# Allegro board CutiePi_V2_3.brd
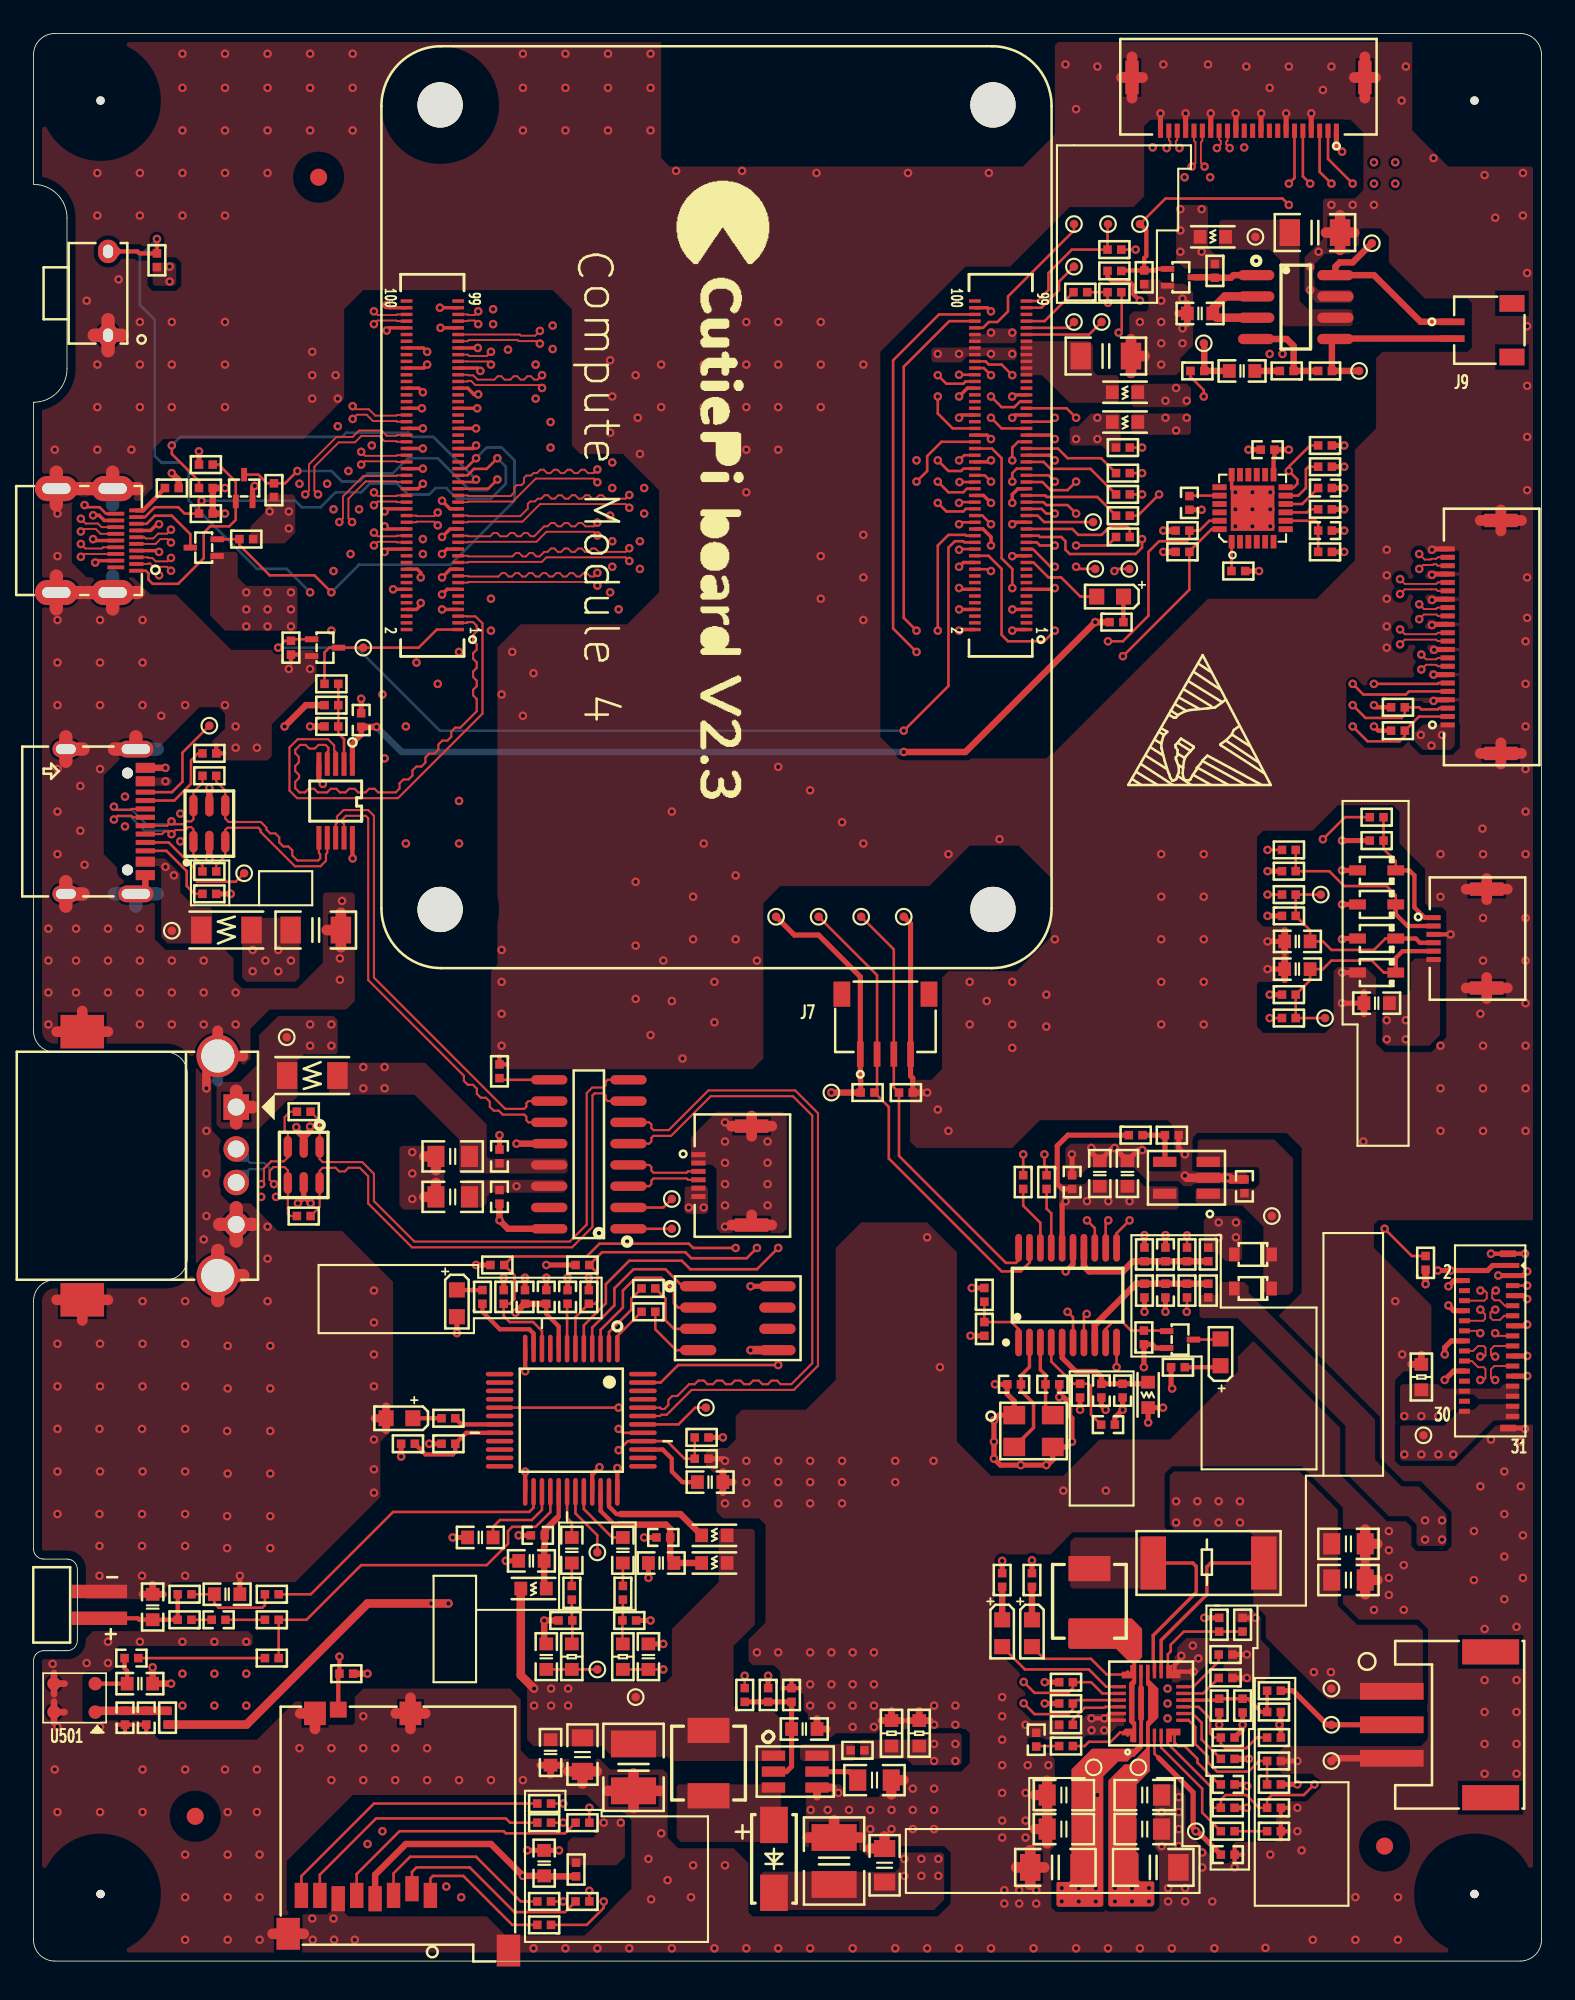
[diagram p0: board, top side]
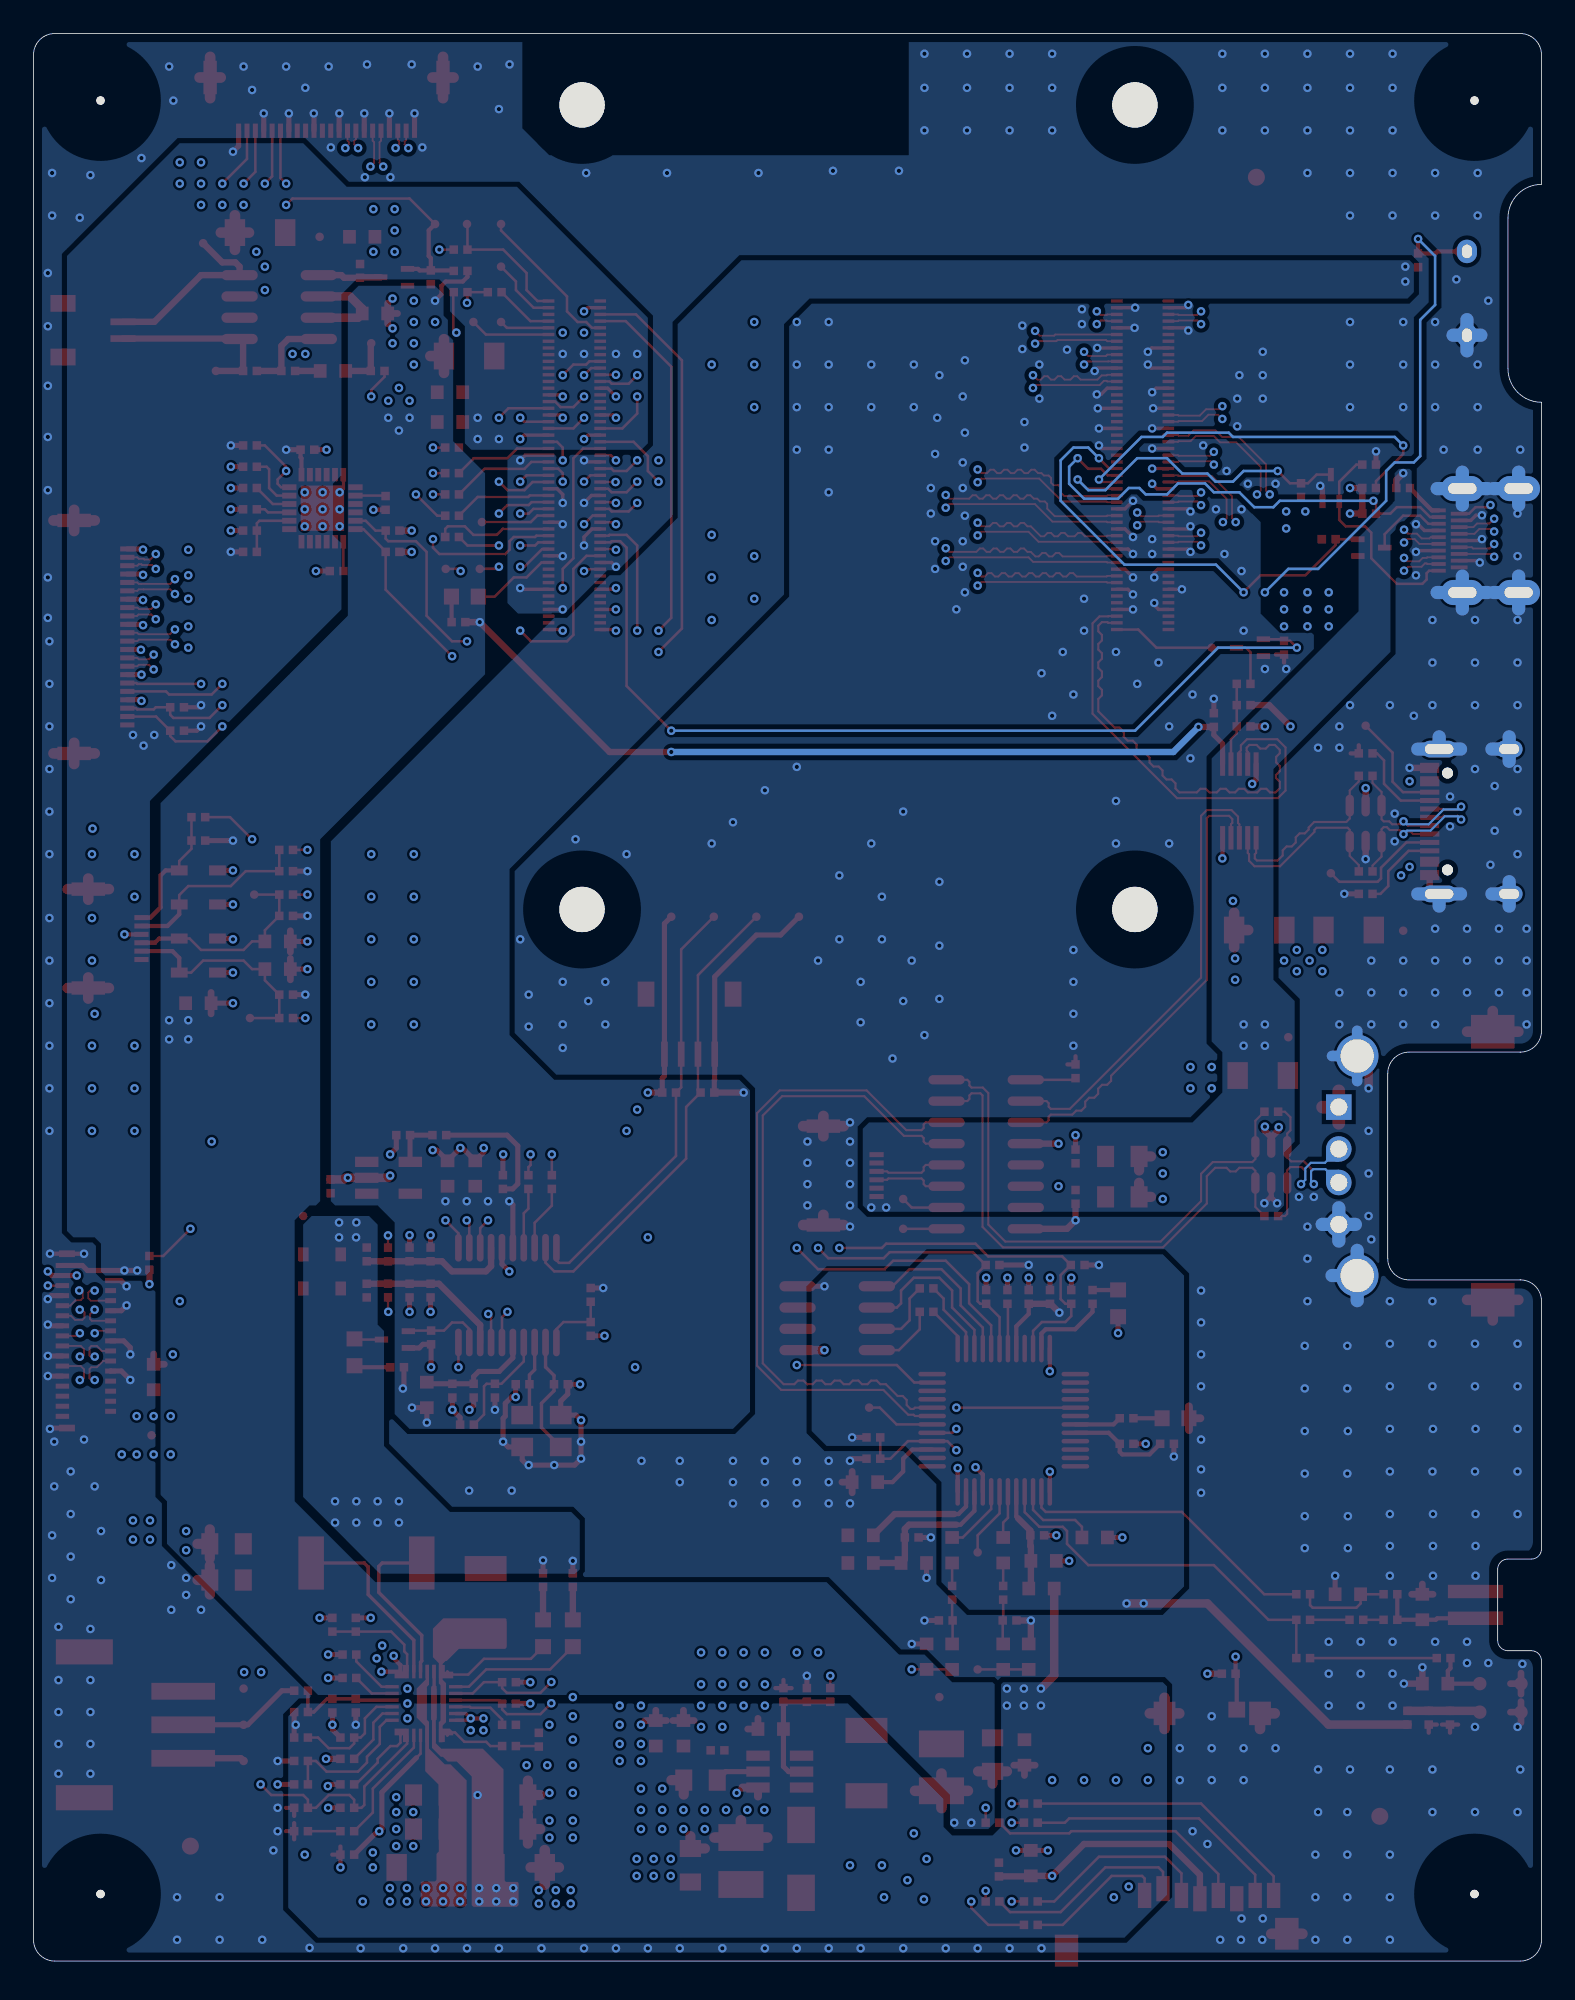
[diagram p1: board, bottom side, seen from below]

Outline 90.01 x 115 mm; copper layers: TOP, GND02, L03, L04, GND05, BOTTOM. Coordinates in mm from the lower left corner of the outline.
Outline path: 0,113.73 arc(0.37,114.63) 1.27,115 88.74,115 arc(89.64,114.63) 90.01,113.73 90.01,1.27 arc(89.64,0.37) 88.74,0 1.27,0 arc(0.37,0.37) 0,1.27 0,17.91 arc(0.18,18.34) 0.61,18.52 1.27,18.52 2.01,18.52 arc(2.44,18.7) 2.62,19.13 2.62,23.37 arc(2.44,23.8) 2.01,23.98 0.61,23.98 arc(0.18,24.16) 0,24.59 0,39.37 arc(0.37,40.27) 1.27,40.64 7.91,40.64 arc(8.81,41.01) 9.18,41.91 9.18,52.96 arc(8.81,53.86) 7.91,54.23 1.27,54.23 arc(0.37,54.6) 0,55.5 0,93 arc(1.41,93.59) 2,95 2,104 arc(1.41,105.41) 0,106 0,113.73

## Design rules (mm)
net group DP_N12951086: nets N12951060 N12951086
net group N13167521: nets N13167521 N13167621
net group RXD0: nets N12403491 RXD0
net group TXD0: nets N12403489 TXD0
net group USB1_: nets USB1_DM USB1_DP
net group USB2_: nets USB2_DM USB2_DP
net group USB3_DM: nets USB3_DM USB3_DP
net group USB_DP: nets USB_DN USB_DP
net group USBH_DP: nets USBH_DN USBH_DP
net group USBS_DN: nets USBS_DN USBS_DP
net group BOOST_EN: nets BOOST_EN CHARGE_EN N12951318
net group CAM0: nets CAM0_CN CAM0_CP CAM0_DN0 CAM0_DN1 CAM0_DP0 CAM0_DP1
net group CAM1: nets CAM1_CN CAM1_CP CAM1_DN0 CAM1_DN1 CAM1_DN2 CAM1_DN3 CAM1_DP0 CAM1_DP1 CAM1_DP2 CAM1_DP3
net group DSI1: nets DSI1_CN DSI1_CP DSI1_DN0 DSI1_DN1 DSI1_DN2 DSI1_DN3 DSI1_DP0 DSI1_DP1 DSI1_DP2 DSI1_DP3
net group HDMI1: nets HDMI_CK_N HDMI_CK_P HDMI_D0_N HDMI_D0_P HDMI_D1_N HDMI_D1_P HDMI_D2_N HDMI_D2_P
net group VBUSA: nets N12836963

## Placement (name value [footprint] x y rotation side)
C2  47u/6.3V  [C1206]  16.85 61.51 0 top
C17  -  [C0402]  19.56 74.04 270 top
C20  47u/6.3V  [C1206]  76.49 103.12 0 top
C24  4.7u/16V  [C0603]  30.48 5.84 90 top
C68  0.1uF/50V  [C0603]  30.86 12.45 270 top
C69  1.0uF/25V  [C0805]  32.77 12.32 270 top
C73  0.1uF/50V  [C0603]  46.01 13.84 0 top
C74  0.22uF/50V  [C0805]  50.2 10.79 0 top
C76  4.7uF/50V  [C1210]  47.79 5.97 90 top
C78  0.22uF/50V  [C0805]  50.8 5.71 90 top
C80  0.1uF/50V  [C0603]  80.17 57.15 180 top
C81  0.1uF/50V  [C0603]  75.44 60.83 180 top
C82  1000pF/50V  [C0603]  75.44 59.18 180 top
C85  4.7uF/50V  [C1210]  35.81 11.56 90 top
C86  4.7u/16V  [C0603]  69.63 98.3 180 top
C87  0.39u/16V  [C0603]  72.14 94.87 0 top
C383  -  [C0402]  77.09 85.34 0 top
C384  -  [C0402]  77.09 87.88 0 top
C385  -  [C0402]  73.66 90.17 180 top
C386  -  [C0402]  68.99 87 90 top
C2474  -  [C0402]  63.74 34.03 270 top
C2475  -  [C0402]  58.53 34.41 180 top
C2476  -  [C0402]  60.82 34.41 0 top
C2477  -  [C0402]  61.99 46.48 90 top
C2478  4.7u/16V  [C0603]  63.64 46.99 90 top
C2479  -  [C0402]  65.01 34.03 270 top
C2480  -  [C0402]  72.28 46.22 90 top
C2481  4.7u/16V  [C0603]  65.29 46.99 90 top
C2483  -  [C0402]  59.85 13.21 270 top
C2484  47u/6.3V  [C1206]  60.99 5.59 180 top
C2485  10u/16V  [C0805]  61.5 7.87 180 top
C2486  10u/16V  [C0805]  61.5 9.91 180 top
C2487  47u/6.3V  [C1206]  66.84 5.59 0 top
C2488  10u/16V  [C0805]  66.33 7.87 0 top
C2489  10u/16V  [C0805]  66.33 9.91 0 top
C2490  10u/16V  [C0805]  78.49 24.89 0 top
C2491  10u/16V  [C0805]  78.49 22.73 0 top
C2492  -  [C0402]  71.28 6.35 0 top
C2493  -  [C0402]  71.28 10.54 0 top
C2495  -  [C0402]  27.81 48.01 90 top
C2496  10u/16V  [C0805]  25.02 48.01 180 top
C2497  10u/16V  [C0805]  25.02 45.59 180 top
C2501  4.7u/16V  [C0603]  29.72 23.88 180 top
C2502  -  [C0402]  30.1 25.4 180 top
C2503  -  [C0402]  37.59 25.27 180 top
C2504  4.7u/16V  [C0603]  37.47 23.75 180 top
C2505  47u/6.3V  [C1206]  64.01 95.76 0 top
C2507  4.7u/16V  [C0603]  26.67 25.27 180 top
C2508  -  [C0402]  6.73 14.52 90 top
C2509  -  [C0402]  5.46 14.52 270 top
C2510  100pF  [C0603]  6.35 16.55 0 top
C2511  -  [C0402]  30.61 39.62 90 top
C2512  -  [C0402]  27.81 45.59 270 top
C2513  val*  [C0603]  40.39 28.57 0 top
C2514  -  [C0402]  29.34 39.62 90 top
C2515  -  [C0402]  31.88 39.62 90 top
C2516  val*  [C0603]  35.18 24.51 270 top
C2517  val*  [C0603]  36.7 18.16 270 top
C2518  val*  [C0603]  32.13 24.51 270 top
C2519  val*  [C0603]  30.61 18.16 90 top
C2520  val*  [C0603]  11.56 21.88 0 top
C2521  -  [C0402]  11.05 20.36 180 top
C2522  val*  [C0603]  7.11 21.12 90 top
C2523  -  [C0402]  64.14 32 0 top
C2524  -  [C0402]  5.84 18.07 180 top
C2525  -  [C0402]  67.56 42.16 90 top
C2526  -  [C0402]  67.56 40 270 top
D1  -  [LED0603]  64.26 81.41 0 top
D10  SS14-M3/61T  [DO-214AC]  44.2 6.1 90 top
D11  ESDLIN1524BJ  [SOD323]  80.17 63.04 0 top
D12  ESDLIN1524BJ  [SOD323]  80.17 65.07 0 top
D13  ESDLIN1524BJ  [SOD323]  80.17 58.97 0 top
D14  ESDLIN1524BJ  [SOD323]  80.17 61.01 0 top
D17  BAT54HT1  [DIO-SOD323]  72.79 40.13 180 top
D18  BAT54HT1  [DIO-SOD323]  72.79 42.16 180 top
D19  -  [LED0603]  70.85 36.32 270 top
D20  -  [LED0603]  57.82 19.56 90 top
D21  -  [LED0603]  59.6 19.56 90 top
D22  -  [LED0603]  25.27 39.24 90 top
D23  -  [LED0603]  21.84 32.38 0 top
F1  6V/2A  [1206]  11.51 61.51 0 top
F2  6V/0.5A  [1206]  16.64 52.83 180 top
FB2  BLM18PG121SH1  [SL0603]  70.39 102.87 0 top
FB7  BLM18PG121SH1  [SL0603]  66.53 33.78 90 top
FB8  BLM18PG121SH1  [SL0603]  40.64 23.75 0 top
FB9  BLM18PG121SH1  [SL0603]  29.84 22.23 180 top
FB10  BLM18PG121SH1  [SL0603]  65.15 93.6 180 top
FB12  BLM18PG121SH1  [SL0603]  65.15 91.82 180 top
FB13  val*  [SL0603]  40.64 25.4 0 top
J2  VAL  [TYPEC_6446_116FH1301]  4.02 67.99 270 top
J7  -  [SH1_0_4]  50.85 54.11 180 top
J9  -  [SH1_0_2]  84.67 97.3 90 top
J11  VAL  [CONFPC22_05MM_FH52_A]  86 79 90 top
J13  467651001  [MICRO_HDMI]  5.53 84.75 270 top
J14  -  [USB_AM]  12.1 47.45 0 top
J16  473521001_sd  [MOLEX_473521001]  21.78 7.81 0 top
J17  FH52-6S-0.5SH  [CONFPC6_05MM_FH52]  85.15 61 90 top
J21  FH26W-31S-0.3SHW  [CONFPC31_03MM_FH26W]  86.85 37 90 top
J23  VAL  [PH2_0_3]  81.07 14.1 270 top
J24  DF40C-100DS-0.4V  [FCI_10033853_CM]  57.73 89.24 270 top
J25  DF40C-100DS-0.4V  [FCI_10033853_CM]  23.81 89.24 270 top
J26  VAL  [CONFPC22_05MM_FH52_A]  72.52 110.79 180 top
J27  VAL  [MIC_4_5]  3.94 21.25 270 top
J28  VAL  [CONFPC6_05MM_FH52]  41.27 46.86 90 top
L5  10uH/20%  [SHC0402]  40.29 11.81 270 top
L634  1.5u  [SHC0402]  63.03 21.46 90 top
NOREF  val  [unnamed]  57.27 110.74 0 top
NOREF#2  -  [#2]  -58.9 96.01 0 top
NOREF#3  -  [#2]  41.4 90.09 270 top
NOREF#4  -  [unnamed]  17.02 106.43 0 top
NOREF#5  -  [#2]  -66.42 -5.33 0 top
NOREF#6  -  [unnamed]  4 4 0 top
NOREF#7  -  [#2]  40.77 86.74 0 top
NOREF#8  val  [unnamed]  24.27 62.74 0 top
NOREF#9  val  [unnamed]  24.27 110.74 0 top
NOREF#10  -  [unnamed]  4 111 0 top
NOREF#11  -  [#2]  -66.42 36.7 0 top
NOREF#12  -  [unnamed]  9.65 8.64 0 top
NOREF#13  val  [unnamed]  57.27 62.74 0 top
NOREF#14  -  [#2]  65.14 70.04 0 top
NOREF#15  -  [unnamed]  86.01 111 0 top
NOREF#16  -  [unnamed]  86.01 4 0 top
NOREF#17  -  [unnamed]  80.64 6.86 0 top
Q3  -  [SOT50P160X90-3N]  10.16 84.33 180 top
Q4  -  [SOT50P160X90-3N]  12.57 87.88 90 top
Q5  -  [SOT50P160X90-3N]  68.44 37.08 0 top
Q6  -  [SOT50P160X90-3N]  68.49 100.46 0 top
Q7  -  [SOT50P160X90-3N]  17.4 78.36 0 top
R3  -  [R0402]  64.64 79.88 0 top
R15  -  [R0402]  12.7 84.84 0 top
R16  -  [R0402]  81.44 74.8 0 top
R17  -  [R0402]  81.44 73.41 0 top
R18  -  [R0402]  14.35 87.76 270 top
R42  -  [R0402]  74.93 66.29 180 top
R43  -  [R0402]  80.17 68.25 180 top
R87  -  [R0402]  45.25 15.88 270 top
R88  -  [R0402]  42.45 15.88 90 top
R89  -  [R0402]  49.18 12.57 180 top
R90  3.3/1%  [R0603]  52.87 13.59 90 top
R91  3.3/1%  [R0603]  51.21 13.59 90 top
R114  -  [R0402]  74.93 65.02 180 top
R115  -  [R0402]  80.17 66.85 180 top
R117  -  [R0402]  74.93 62.36 0 top
R118  -  [R0402]  74.93 57.66 0 top
R120  -  [R0402]  74.93 56.26 180 top
R121  -  [R0402]  74.93 63.63 180 top
R122  -  [R0402]  16.13 44.45 180 top
R123  -  [R0402]  16.13 50.67 180 top
R124  -  [R0402]  70.52 100.84 270 top
R125  -  [R0402]  77.09 94.87 180 top
R126  -  [R0402]  74.8 94.87 180 top
R127  -  [R0402]  69.47 94.87 0 top
R272  -  [R0402]  62.47 34.03 270 top
R368  -  [R0402]  71.92 82.93 180 top
R370  -  [R0402]  77.09 84.07 180 top
R371  -  [R0402]  77.09 89.15 180 top
R373  -  [R0402]  77.09 86.61 180 top
R3039  -  [R0402]  56.75 37.71 270 top
R3040  -  [R0402]  56.75 39.75 90 top
R3041  -  [R0402]  60.47 46.48 270 top
R3042  -  [R0402]  59.07 46.48 270 top
R3043  -  [R0402]  49.78 51.82 0 top
R3044  -  [R0402]  52.07 51.82 0 top
R3049  -  [R0402]  67.94 49.28 180 top
R3051  -  [R0402]  65.79 49.28 0 top
R3052  -  [R0402]  70.12 42.16 90 top
R3053  -  [R0402]  66.31 42.16 90 top
R3054  -  [R0402]  7.37 101.47 270 top
R3057  -  [R0402]  83.09 41.66 90 top
R3058  -  [R0402]  8.26 87.88 0 top
R3059  -  [R0402]  66.28 37.21 90 top
R3060  -  [R0402]  68.31 35.43 0 top
R3061  -  [R0402]  66.29 100.46 90 top
R3062  -  [R0402]  10.29 89.28 0 top
R3063  NC_3.3/1%  [R0603]  82.84 34.84 90 top
R3064  -  [R0402]  70.12 40 270 top
R3065  -  [R0402]  66.31 40 270 top
R3066  -  [R0402]  43.85 15.88 270 top
R3086  -  [R0402]  74.04 13.34 180 top
R3087  -  [R0402]  61.63 12.83 0 top
R3088  -  [R0402]  71.28 13.34 180 top
R3089  20m/1W  [R2512]  70.14 23.75 0 top
R3090  -  [R0402]  74.04 11.94 180 top
R3091  -  [R0402]  74.04 10.54 0 top
R3092  -  [R0402]  74.04 9.14 180 top
R3093  -  [R0402]  71.28 9.14 0 top
R3094  -  [R0402]  61.63 16.64 180 top
R3095  -  [R0402]  57.82 22.73 90 top
R3096  -  [R0402]  61.63 15.37 180 top
R3097  -  [R0402]  71.28 12.06 0 top
R3098  -  [R0402]  74.04 16.13 180 top
R3099  -  [R0402]  61.63 14.1 0 top
R3100  -  [R0402]  59.6 22.73 90 top
R3101  -  [R0402]  70.77 15.24 90 top
R3102  -  [R0402]  70.77 20.07 270 top
R3103  -  [R0402]  72.17 15.24 90 top
R3104  -  [R0402]  72.17 20.07 270 top
R3105  -  [R0402]  71.28 7.75 180 top
R3106  -  [R0402]  71.15 16.89 180 top
R3107  -  [R0402]  71.15 18.29 180 top
R3108  -  [R0402]  74.04 7.75 0 top
R3132  -  [R0402]  18.67 17.14 0 top
R3133  -  [R0402]  10.5 72.05 0 top
R3134  -  [R0402]  10.5 63.67 0 top
R3137  -  [R0402]  74.04 14.86 180 top
R3138  -  [R0402]  30.48 2.16 180 top
R3139  -  [R0402]  32.77 3.56 180 top
R3140  -  [R0402]  30.48 3.56 180 top
R3141  -  [R0402]  32.77 8.26 180 top
R3142  -  [R0402]  30.48 8.26 180 top
R3143  -  [R0402]  30.48 9.4 180 top
R3145  -  [R0402]  64.52 100.84 180 top
R3149  -  [R0402]  27.81 53.09 270 top
R3153  -  [R0402]  32.38 5.46 270 top
R3154  -  [R0402]  68.85 42.16 90 top
R3155  -  [R0402]  68.85 40 270 top
R3156  -  [R0402]  62.48 99.57 180 top
R3157  -  [R0402]  65.02 90.3 0 top
R3158  -  [R0402]  8 14.52 90 top
R3160  -  [R0402]  33.15 39.62 270 top
R3161  -  [R0402]  10.5 70.71 0 top
R3162  -  [R0402]  10.5 65.01 0 top
R3163  -  [R0402]  17.78 73.66 0 top
R3164  -  [R0402]  17.78 74.93 180 top
R3165  -  [R0402]  68.58 85.34 180 top
R3166  -  [R0402]  68.58 84.07 180 top
R3167  -  [R0402]  77.09 90.42 180 top
R3168  -  [R0402]  10.29 87.88 0 top
R3169  -  [R0402]  10.29 86.36 0 top
R3172  -  [R0402]  17.78 76.2 0 top
R3173  -  [R0402]  32.77 41.53 180 top
R3174  -  [R0402]  36.7 38.73 180 top
R3175  -  [R0402]  36.7 40.13 180 top
R3176  -  [R0402]  27.69 41.53 180 top
R3177  -  [R0402]  28.07 39.62 270 top
R3178  -  [R0402]  26.8 39.62 90 top
R3179  -  [R0402]  24.77 32.38 180 top
R3180  -  [R0402]  22.35 30.86 180 top
R3181  -  [R0402]  24.77 30.86 0 top
R3182  -  [R0402]  39.88 31.24 0 top
R3183  -  [R0402]  39.88 29.97 180 top
R3184  val*  [R0603]  35.18 18.16 270 top
R3185  -  [R0402]  35.18 21.97 270 top
R3186  -  [R0402]  35.56 20.32 0 top
R3187  -  [R0402]  32.13 21.97 270 top
R3188  val*  [R0603]  32.13 18.16 270 top
R3189  -  [R0402]  31.75 20.32 0 top
R3190  -  [R0402]  14.22 21.88 180 top
R3191  -  [R0402]  9.02 20.36 180 top
R3192  -  [R0402]  9.02 21.88 180 top
R3193  -  [R0402]  64.52 102.11 180 top
R3194  -  [R0402]  65.02 88.77 180 top
R3195  -  [R0402]  65.02 87.5 180 top
R3196  -  [R0402]  15.37 78.36 90 top
R3197  -  [R0402]  65.02 84.96 0 top
R3198  -  [R0402]  65.02 86.23 180 top
R3199  -  [R0402]  14.22 18.07 180 top
R3200  -  [R0402]  14.22 20.36 180 top
R3201  -  [R0402]  64.52 99.57 0 top
SW2  TC-0143  [BUTTON]  4.45 99.5 270 top
TP28  VAL  [TESTPOINT_20MIL]  76.83 63.63 90 top
TP29  VAL  [TESTPOINT_20MIL]  77.09 56.26 90 top
TP30  VAL  [TESTPOINT_20MIL]  35.94 15.75 270 top
TP33  VAL  [TESTPOINT_20MIL]  82.96 31.37 0 top
TP41  VAL  [TESTPOINT_20MIL]  8.26 61.47 0 top
TP43  VAL  [TESTPOINT_20MIL]  63.28 11.56 0 top
TP44  VAL  [TESTPOINT_20MIL]  77.47 16.26 0 top
TP45  VAL  [TESTPOINT_20MIL]  69.38 7.75 0 top
TP46  VAL  [TESTPOINT_20MIL]  65.95 11.56 0 top
TP47  VAL  [TESTPOINT_20MIL]  77.47 14.1 0 top
TP52  VAL  [TESTPOINT_20MIL]  15.11 55.12 0 top
TP57  VAL  [TESTPOINT_20MIL]  72.93 102.87 90 top
TP58  VAL  [TESTPOINT_20MIL]  69.85 96.52 90 top
TP59  VAL  [TESTPOINT_20MIL]  66.04 103.63 90 top
TP60  VAL  [TESTPOINT_20MIL]  79.12 94.87 0 top
TP61  VAL  [TESTPOINT_20MIL]  79.88 102.49 0 top
TP62  VAL  [TESTPOINT_20MIL]  46.86 62.31 0 top
TP63  VAL  [TESTPOINT_20MIL]  49.4 62.31 0 top
TP64  VAL  [TESTPOINT_20MIL]  73.91 44.45 0 top
TP65  VAL  [TESTPOINT_20MIL]  47.62 51.82 0 top
TP77  VAL  [TESTPOINT_20MIL]  63.75 97.79 90 top
TP78  VAL  [TESTPOINT_20MIL]  62.1 97.79 90 top
TP79  VAL  [TESTPOINT_20MIL]  62.1 101.09 90 top
TP80  VAL  [TESTPOINT_20MIL]  64.14 103.63 90 top
TP81  VAL  [TESTPOINT_20MIL]  33.66 24.38 270 top
TP83  VAL  [TESTPOINT_20MIL]  62.1 103.63 90 top
TP84  VAL  [TESTPOINT_20MIL]  65.41 83.06 90 top
TP89  VAL  [TESTPOINT_20MIL]  63.37 83.06 90 top
TP90  VAL  [TESTPOINT_20MIL]  63.25 85.85 90 top
TP91  VAL  [TESTPOINT_20MIL]  77.47 11.94 0 top
TP92  VAL  [TESTPOINT_20MIL]  10.5 73.7 0 top
TP93  VAL  [TESTPOINT_20MIL]  12.57 64.9 0 top
TP94  VAL  [TESTPOINT_20MIL]  19.68 78.36 0 top
TP95  VAL  [TESTPOINT_20MIL]  40.13 33.02 180 top
TP97  VAL  [TESTPOINT_20MIL]  33.66 17.4 180 top
TP98  VAL  [TESTPOINT_20MIL]  44.32 62.31 0 top
TP99  VAL  [TESTPOINT_20MIL]  51.94 62.31 0 top
TP100  VAL  [TESTPOINT_20MIL]  38.1 43.69 90 top
TP101  VAL  [TESTPOINT_20MIL]  38.1 45.47 90 top
U3  CM108AH  [QFN48_05MM_0707MMLTS]  32.1 32.27 270 top
U5  IP4234CZ6  [TSOP6]  16.13 47.5 180 top
U6  -  [SOT23_6B]  45.47 11.3 270 top
U12  LM4871MX  [SOIC8_1D27MM]  75.34 98.68 270 top
U18  stm32f030f4p6  [TSSOP20_0D65MM]  61.72 39.73 0 top
U57  MPU6050  [QFN24_05MM_0404MML]  72.76 86.68 90 top
U60  -  [SOT23_5]  68.82 46.73 90 top
U501  -  [LGA5_CAV_4P1X3P1MM]  3.68 16.55 270 top
U580  AT93C46  [SOIC8]  42.04 38.35 270 top
U597  MP2636GR  [QFN-30]  66.71 15.37 90 top
U600  val  [SOP16_1P27_HS8836A]  33.15 48.13 90 top
U601  val  [TSOP6]  10.5 67.86 0 top
U602  -  [SOP10_20_120A]  18.03 69.22 180 top
Y2  -  [XTAL_3225_25M_A]  59.69 31.62 180 top

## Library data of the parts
C2 C20 C2484 C2487 C2505 = CAP_3216_6.3V_47u: Tolerance: tol*
C17 C383-C386 C2474 C2477 C2479 C2483 C2492 C2493 C2495 C2502 C2503 C2508 C2509 C2511 C2512 C2514 C2515 C2521 C2523-C2526 = CAP_1005_6.3V_100n
C24 C86 C87 C2478 C2481 C2501 C2504 C2507 C2513 C2516 C2518 C2520 = CAP_1608_6.3V_4.7u: Tolerance: tol*
C68 C69 C73 C74 C76 C78 C82 C85 C2510 C2517 C2519 C2522 = CAP: Tolerance: tol*
C80 C81 = CAP_0: Tolerance: tol*
C2475 C2476 = C_0603_22P/50V/5%
C2480 = CAP_1005_6.3V_1u
C2485 C2486 C2488-C2491 C2496 C2497 = CAP_2012_6.3V_10u: Tolerance: tol*
D1 = LED_1608_RED_0
D10 = S100: User Part Number: pn
D11-D14 = SMAJ30CA: User Part Number: PN
D17 D18 = DIODE_0: User Part Number: PN
D19-D23 = LED_1608_GREEN_0
F1 F2 = FUSE_POLY_2.0A_6V: Tolerance: tol*
FB2 FB7-FB10 FB12 FB13 = INDUCTOR_0: Tolerance: tol*; room: USB+5V
J2 = CON_HDMI_RA_3: User Part Number: PN
J7 = A2002WV-6P_7
J9 = A2002WV-6P_8
J11 J26 = CON_22W_FFC_0: User Part Number: PN
J13 = CON_HDMI_RA: User Part Number: PN
J14 = CON_USBA_RA_PTH_0
J16 = CON_uSD_2: User Part Number: PN
J17 J28 = A2002WV-6P_3: User Part Number: PN
J21 = CON32_1: User Part Number: PN
J23 = A2002WV-6P_4: User Part Number: PN
J24 J25 = CON_200W_DDR2SODIMM_CM_2: User Part Number: PN
J27 = A2002WV-6P_8: User Part Number: PN
L5 = IND: User Part Number: pn
L634 = IND_4u7_SRN4018-4R7M: User Part Number: pn
NOREF NOREF#8 NOREF#9 NOREF#13 = -: User Part Number: pn
Q3-Q7 = MOSFET_N_DMG1012T
R3 R3060 R3178 R3179 = RES_1005_470R
R15 R18 R3059 R3061 R3062 R3133 R3134 R3145 R3160 R3173 R3176 R3177 R3180-R3183 R3196 = RES_1005_100K
R16 R17 = RES_1005_1.8K
R42 R43 R87-R89 R120-R123 R127 R368 R370 R371 R373 R3052 R3057 R3064 R3066 R3086-R3088 R3090-R3093 R3095 R3097-R3108 R3137 R3149 R3153-R3158 R3161-R3164 R3167 R3172 R3174 R3175 R3185-R3187 R3189-R3195 R3197-R3201 = RES
R90 R91 R3063 R3089 R3184 R3188 = RES: Tolerance: tol*
R114 R115 R117 R118 R124-R126 R3049 R3051 R3053 R3065 R3165 R3166 R3168 R3169 = RES_0
R272 R3054 = R_0603_10K/5%
R3039 R3040 = R_0402_22R/5%
R3041 R3042 R3058 R3094 R3096 = R_1: signal model: DEFAULT_RESISTOR_0.001OHM_1_2
R3043 R3044 = R_0603/4.7K/5%
R3132 R3138-R3143 = RES_1005_47K
SW2 = SKEG_DIP2_2: User Part Number: PN
TP28-TP30 TP33 TP41 TP43-TP47 TP52 TP57-TP65 TP77-TP81 TP83 TP84 TP89-TP95 TP97-TP101 = Test pad: Tolerance: *; User Part Number: PN; room: P10-PMIC
U3 = LSD4WF-00007010_2: User Part Number: pn
U5 U601 = TMP100-Q1_0: User Part Number: pn
U6 = TPS61165TDB
U12 = SMD_EEPROM_SO8_0: User Part Number: pn
U18 = XF6000SYE_1: User Part Number: pn
U57 = TUSB1210BRHBT_2: User Part Number: PN
U60 = LP3470/SOT23_1
U501 = ADMP421_LGA5_1
U580 = PCA9306IDCURQ1_0: User Part Number: pn
U597 = STM8AF6226TA_5: User Part Number: PN
U600 = NEO-M8L_2: User Part Number: pn
U602 = IC_MUX2-1_USB_0
Y2 = X_0

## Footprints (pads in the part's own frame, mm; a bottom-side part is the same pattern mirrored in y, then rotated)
1206
  rect 1.219x1.6 smd: 1(-1.5,0) 2(1.5,0)
BUTTON
  oval 1.4x1.2 hole 0.8x0.6: 1(2.5,0) 2(-2.5,0)
C0402
  rect 0.508x0.508 smd: 1(-0.41,0) 2(0.41,0)
C0603
  rect 0.762x0.813 smd: 1(-0.76,0) 2(0.76,0)
C0805
  rect 1.016x1.27 smd: 1(-1,0) 2(1,0)
C1206
  rect 1.219x1.6 smd: 1(-1.5,0) 2(1.5,0)
C1210
  rect 1.6x2.692 smd: 1(-1.4,0) 2(1.4,0)
CONFPC6_05MM_FH52
  rect 0.3x0.85 smd: 1(1.25,1.587) 2(0.75,1.587) 3(0.25,1.587) 4(-0.25,1.587) 5(-0.75,1.587) 6(-1.25,1.587)
  rect 0.8x2 smd: 7(-2.95,-1.587) 8(2.95,-1.587)
CONFPC22_05MM_FH52_A
  rect 0.3x0.85 smd: 1(5.25,1.587) 2(4.75,1.587) 3(4.25,1.587) 4(3.75,1.587) 5(3.25,1.587) 6(2.75,1.587) 7(2.25,1.587) 8(1.75,1.587) 9(1.25,1.587) 10(0.75,1.587) 11(0.25,1.587) 12(-0.25,1.587) 13(-0.75,1.587) 14(-1.25,1.587) 15(-1.75,1.587) 16(-2.25,1.587) 17(-2.75,1.587) 18(-3.25,1.587) 19(-3.75,1.587) 20(-4.25,1.587) 21(-4.75,1.587) 22(-5.25,1.587)
  rect 0.8x2 smd: G1(-6.95,-1.587) G2(6.95,-1.587)
CONFPC31_03MM_FH26W
  rect 0.3x0.8 smd: 1(4.5,-1.437) 3(3.9,-1.437) 5(3.3,-1.437) 7(2.7,-1.437) 9(2.1,-1.437) 11(1.5,-1.437) 13(0.9,-1.437) 15(0.3,-1.437) 17(-0.3,-1.437) 19(-0.9,-1.437) 21(-1.5,-1.437) 23(-2.1,-1.437) 25(-2.7,-1.437) 27(-3.3,-1.437) 29(-3.9,-1.437) 31(-4.5,-1.437)
  rect 0.3x0.65 smd: 2(4.2,1.437) 4(3.6,1.437) 6(3,1.437) 8(2.4,1.437) 10(1.8,1.437) 12(1.2,1.437) 14(0.6,1.437) 16(0,1.437) 18(-0.6,1.437) 20(-1.2,1.437) 22(-1.8,1.437) 24(-2.4,1.437) 26(-3,1.437) 28(-3.6,1.437) 30(-4.2,1.437)
  rect 0.4x0.95 smd: G1(-5.2,-1.165) G2(5.2,-1.165)
DIO-SOD323
  rect 0.63x0.83 smd: 1(-1.115,0) 2(1.115,0)
DO-214AC
  rect 2.17x1.65 smd: A(2.025,0) C(-2.025,0)
FCI_10033853_CM
  rect 0.2x0.7 smd: 1(9.8,1.54) 2(9.8,-1.54) 3(9.4,1.54) 4(9.4,-1.54) 5(9,1.54) 6(9,-1.54) 7(8.6,1.54) 8(8.6,-1.54) 9(8.2,1.54) 10(8.2,-1.54) 11(7.8,1.54) 12(7.8,-1.54) 13(7.4,1.54) 14(7.4,-1.54) 15(7,1.54) 16(7,-1.54) 17(6.6,1.54) 18(6.6,-1.54) 19(6.2,1.54) 20(6.2,-1.54) 21(5.8,1.54) 22(5.8,-1.54) 23(5.4,1.54) 24(5.4,-1.54) 25(5,1.54) 26(5,-1.54) 27(4.6,1.54) 28(4.6,-1.54) 29(4.2,1.54) 30(4.2,-1.54) 31(3.8,1.54) 32(3.8,-1.54) 33(3.4,1.54) 34(3.4,-1.54) 35(3,1.54) 36(3,-1.54) 37(2.6,1.54) 38(2.6,-1.54) 39(2.2,1.54) 40(2.2,-1.54) 41(1.8,1.54) 42(1.8,-1.54) 43(1.4,1.54) 44(1.4,-1.54) 45(1,1.54) 46(1,-1.54) 47(0.6,1.54) 48(0.6,-1.54) 49(0.2,1.54) 50(0.2,-1.54) 51(-0.2,1.54) 52(-0.2,-1.54) 53(-0.6,1.54) 54(-0.6,-1.54) 55(-1,1.54) 56(-1,-1.54) 57(-1.4,1.54) 58(-1.4,-1.54) 59(-1.8,1.54) 60(-1.8,-1.54) 61(-2.2,1.54) 62(-2.2,-1.54) 63(-2.6,1.54) 64(-2.6,-1.54) 65(-3,1.54) 66(-3,-1.54) 67(-3.4,1.54) 68(-3.4,-1.54) 69(-3.8,1.54) 70(-3.8,-1.54) 71(-4.2,1.54) 72(-4.2,-1.54) 73(-4.6,1.54) 74(-4.6,-1.54) 75(-5,1.54) 76(-5,-1.54) 77(-5.4,1.54) 78(-5.4,-1.54) 79(-5.8,1.54) 80(-5.8,-1.54) 81(-6.2,1.54) 82(-6.2,-1.54) 83(-6.6,1.54) 84(-6.6,-1.54) 85(-7,1.54) 86(-7,-1.54) 87(-7.4,1.54) 88(-7.4,-1.54) 89(-7.8,1.54) 90(-7.8,-1.54) 91(-8.2,1.54) 92(-8.2,-1.54) 93(-8.6,1.54) 94(-8.6,-1.54) 95(-9,1.54) 96(-9,-1.54) 97(-9.4,1.54) 98(-9.4,-1.54) 99(-9.8,1.54) 100(-9.8,-1.54)
LED0603
  rect 0.9x0.95 smd: 1(0.8,0) 2(-0.8,0)
LGA5_CAV_4P1X3P1MM
  round 0.8 smd: 1(1.7,0) 2(1.7,-2.46) 3(0,-2.46) 4(0,0)
MIC_4_5
  rect 0.8x3.3 smd: 1(-0.8,0) 2(0.8,0)
MICRO_HDMI
  rect 0.23x0.85 smd: 1(1.8,0.612) 3(1.4,0.612) 5(1,0.612) 7(0.6,0.612) 9(0.2,0.612) 11(-0.2,0.612) 13(-0.6,0.612) 15(-1,0.612) 17(-1.4,0.612) 19(-1.8,0.612)
  rect 0.23x1 smd: 2(1.6,-0.612) 4(1.2,-0.612) 6(0.8,-0.612) 8(0.4,-0.612) 10(0,-0.612) 12(-0.4,-0.612) 14(-0.8,-0.612) 16(-1.2,-0.612) 18(-1.6,-0.612)
  oval 1.5x2.55 hole 0.65x1.7: 20(3.1,-4.163) 21(-3.1,-0.802) 22(3.1,-0.802) 23(-3.1,-4.163)
MOLEX_473521001
  rect 0.8x1.5 smd: 1(1.915,-3.898) 2(0.815,-3.498) 3(-0.285,-3.898) 4(-1.385,-4.098) 5(-2.485,-3.898) 6(-3.585,-4.098) 7(-4.685,-3.898) 8(-5.785,-3.898)
  rect 1x0.95 smd: 9(-3.585,7.187)
  rect 1.4x1.9 smd: 10(6.575,-7.187) 11(-6.575,-6.187)
  rect 1.3x1.4 smd: 12(-4.975,6.962) 13(0.725,6.962)
PH2_0_3
  rect 1.501x3.401 smd: (-4.351,5.9) (4.351,5.9)
  rect 1.001x3.8 smd: 1(-1.999,0) 2(0,0) 3(1.999,0)
QFN24_05MM_0404MML
  rect 0.8x0.35 smd: 1(-2,1.25) 2(-2,0.75) 3(-2,0.25) 4(-2,-0.25) 5(-2,-0.75) 6(-2,-1.25) 13(2,-1.25) 14(2,-0.75) 15(2,-0.25) 16(2,0.25) 17(2,0.75) 18(2,1.25)
  rect 0.35x0.85 smd: 7(-1.25,-1.975) 8(-0.75,-1.975) 9(-0.25,-1.975) 10(0.25,-1.975) 11(0.75,-1.975) 12(1.25,-1.975) 19(1.25,1.975) 20(0.75,1.975) 21(0.25,1.975) 22(-0.25,1.975) 23(-0.75,1.975) 24(-1.25,1.975)
  rect 2.7x2.6 smd: 25(0,0)
QFN48_05MM_0707MMLTS
  oval 1.65x0.27 smd: 1(-4.275,2.75) 2(-4.275,2.25) 3(-4.275,1.75) 4(-4.275,1.25) 5(-4.275,0.75) 6(-4.275,0.25) 7(-4.275,-0.25) 8(-4.275,-0.75) 9(-4.275,-1.25) 10(-4.275,-1.75) 11(-4.275,-2.25) 12(-4.275,-2.75) 25(4.275,-2.75) 26(4.275,-2.25) 27(4.275,-1.75) 28(4.275,-1.25) 29(4.275,-0.75) 30(4.275,-0.25) 31(4.275,0.25) 32(4.275,0.75) 33(4.275,1.25) 34(4.275,1.75) 35(4.275,2.25) 36(4.275,2.75)
  oval 0.27x1.65 smd: 13(-2.75,-4.275) 14(-2.25,-4.275) 15(-1.75,-4.275) 16(-1.25,-4.275) 17(-0.75,-4.275) 18(-0.25,-4.275) 19(0.25,-4.275) 20(0.75,-4.275) 21(1.25,-4.275) 22(1.75,-4.275) 23(2.25,-4.275) 24(2.75,-4.275) 37(2.75,4.275) 38(2.25,4.275) 39(1.75,4.275) 40(1.25,4.275) 41(0.75,4.275) 42(0.25,4.275) 43(-0.25,4.275) 44(-0.75,4.275) 45(-1.25,4.275) 46(-1.75,4.275) 47(-2.25,4.275) 48(-2.75,4.275)
QFN-30
  custom 0.175x0.175 smd: 1(-1.9,1.4) 8(-1.9,-1.4) 15(1.9,-1.4) 22(1.9,1.4)
  rect 0.8x0.2 smd: 2(-1.9,1) 3(-1.9,0.6) 4(-1.9,0.2) 5(-1.9,-0.2) 6(-1.9,-0.6) 7(-1.9,-1) 16(1.9,-1) 17(1.9,-0.6) 18(1.9,-0.2) 19(1.9,0.2) 20(1.9,0.6) 21(1.9,1)
  rect 0.2x0.8 smd: 9(-1,-1.9) 10(-0.6,-1.9) 11(-0.2,-1.9) 12(0.2,-1.9) 13(0.6,-1.9) 14(1,-1.9) 23(1,1.9) 24(0.6,1.9) 25(0.2,1.9) 26(-0.2,1.9) 27(-0.6,1.9) 28(-1,1.9)
  rect 1.8x0.3 smd: 29(0,0.6) 30(0,0)
R0402
  rect 0.508x0.508 smd: 1(-0.41,0) 2(0.41,0)
R0603
  rect 0.762x0.813 smd: 1(-0.76,0) 2(0.76,0)
R2512
  rect 1.524x3.175 smd: 1(-3.3,0) 2(3.3,0)
SH1_0_2
  rect 1x1.5 smd: (-1.6,-3.58) (1.6,-3.58)
  rect 0.4x1.5 smd: 1(0.5,0) 2(-0.5,0)
SH1_0_4
  rect 1x1.5 smd: (-2.6,-3.58) (2.6,-3.58)
  rect 0.4x1.5 smd: 1(1.5,0) 2(0.5,0) 3(-0.5,0) 4(-1.5,0)
SHC0402
  rect 1.5x2.5 smd: 1(-1.95,0) 2(1.95,0)
SL0603
  rect 0.762x0.813 smd: 1(-0.76,0) 2(0.76,0)
SOD323
  rect 1x0.6 smd: A(-1.14,0) C(1.14,0)
SOIC8
  oval 0.61x2.17 smd: 1(-1.905,-2.365) 2(-0.635,-2.365) 3(0.635,-2.365) 4(1.905,-2.365) 5(1.905,2.365) 6(0.635,2.365) 7(-0.635,2.365) 8(-1.905,2.365)
SOIC8_1D27MM
  oval 0.61x2.17 smd: 1(-1.905,-2.365) 2(-0.635,-2.365) 3(0.635,-2.365) 4(1.905,-2.365) 5(1.905,2.365) 6(0.635,2.365) 7(-0.635,2.365) 8(-1.905,2.365)
SOP10_20_120A
  rect 0.3x1.4 smd: 1(-1,-2.2) 2(-0.5,-2.2) 3(0,-2.2) 4(0.5,-2.2) 5(1,-2.2) 6(1,2.2) 7(0.5,2.2) 8(0,2.2) 9(-0.5,2.2) 10(-1,2.2)
SOP16_1P27_HS8836A
  oval 0.56x2.17 smd: 1(-4.445,-2.365) 2(-3.175,-2.365) 3(-1.905,-2.365) 4(-0.635,-2.365) 5(0.635,-2.365) 6(1.905,-2.365) 7(3.175,-2.365) 8(4.445,-2.365) 9(4.445,2.365) 10(3.175,2.365) 11(1.905,2.365) 12(0.635,2.365) 13(-0.635,2.365) 14(-1.905,2.365) 15(-3.175,2.365) 16(-4.445,2.365)
SOT23_5
  rect 0.61x1.397 smd: 1(-0.95,-1.3) 2(0,-1.3) 3(0.95,-1.3) 4(0.95,1.3) 5(-0.95,1.3)
SOT23_6B
  rect 0.61x1.397 smd: 1(-0.95,-1.3) 2(0,-1.3) 3(0.95,-1.3) 4(0.95,1.3) 5(0,1.3) 6(-0.95,1.3)
SOT50P160X90-3N
  rect 0.8x0.35 smd: 1(-0.8,0.5) 2(-0.8,-0.5) 3(0.8,0)
TESTPOINT_20MIL
  round 0.508 smd: 1(0,0)
TSOP6
  oval 0.5x1.3 smd: 1(-0.95,-1.075) 2(0,-1.075) 3(0.95,-1.075) 4(0.95,1.075) 5(0,1.075) 6(-0.95,1.075)
TSSOP20_0D65MM
  oval 0.4x1.65 smd: 1(-2.925,-2.825) 2(-2.275,-2.825) 3(-1.625,-2.825) 4(-0.975,-2.825) 5(-0.325,-2.825) 6(0.325,-2.825) 7(0.975,-2.825) 8(1.625,-2.825) 9(2.275,-2.825) 10(2.925,-2.825) 11(2.925,2.825) 12(2.275,2.825) 13(1.625,2.825) 14(0.975,2.825) 15(0.325,2.825) 16(-0.325,2.825) 17(-0.975,2.825) 18(-1.625,2.825) 19(-2.275,2.825) 20(-2.925,2.825)
TYPEC_6446_116FH1301
  round 0.65 hole 0.65 unplated: (-2.89,1.59) (2.89,1.59)
  rect 0.6x1.15 smd: A1_B12(-3.2,2.655) A4_B9(-2.4,2.655) B1_A12(3.2,2.655) B4_A9(2.4,2.655)
  rect 0.3x1.15 smd: A5(-1.25,2.655) A6(-0.25,2.655) A7(0.25,2.655) A8(1.25,2.655) B5(1.75,2.655) B6(0.75,2.655) B7(-0.75,2.655) B8(-1.75,2.655)
  oval 1x2.1 hole 0.6x1.7: G1(-4.32,2.09) G2(4.32,2.09)
  oval 1x1.6 hole 0.6x1.2: G3(-4.32,-2.09) G4(4.32,-2.09)
unnamed
  round 2.7 hole 2.7 unplated: (0,0)
USB_AM
  rect 1.524x1.524 hole 1.016: 1(0,3.5)
  round 1.524 hole 1.016: 2(0,1) 3(0,-1) 4(0,-3.5)
  round 2.54 hole 1.981: 5(-1.1,6.55) 6(-1.1,-6.55)
  rect 2.6x2 smd: 7(-9.189,8) 8(-9.189,-8)
XTAL_3225_25M_A
  rect 1.3x1.1 smd: 1(-1.15,-0.95) 2(1.15,-0.95) 3(1.15,0.95) 4(-1.15,0.95)

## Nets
3V3: C17.2 C80.1 FB12.1 J17.6 R3.1 R114.2 R115.2 R117.1 R118.1 R3066.1(A) R3145.2 R3153.1(A) U602.1(VCC)
3V3_SD: C24.1 J16.4(VDD) R3132.2 R3153.2(B)
5V_IN: C2.1 C2487.1 C2488.1 C2489.1 D17.2 F1.2(P2) R3064.2(B) R3091.2(B) R3093.2(B) R3164.2(B) TP46.1(PIN1) U597.4(VIN1) U597.19(VIN3) U597.30(VIN2) U601.5(PW)
GND: C2.2 C17.1 C20.2 C24.2 C68.2 C69.2 C73.2 C74.2 C76.2 C78.2 C80.2 C81.2 C82.2 C85.1 C86.2 C383.2 C384.2 C385.2 C386.1 C2474.2 C2475.2 C2476.2 C2477.2 C2478.2 C2479.2 C2480.2 C2481.2 C2483.1 C2484.2 C2485.2 C2486.2 C2487.2 C2488.2 C2489.2 C2490.2 C2491.2 C2492.2 C2493.2 C2495.2 C2496.2 C2497.2 C2501.2 C2502.2 C2503.2 C2504.2 C2505.2 C2507.2 C2508.1 C2509.2 C2510.2 C2511.2 C2512.2 C2513.2 C2514.2 C2515.2 C2517.1 C2519.2 C2520.2 C2522.2 C2523.2 C2525.2 C2526.2 D11.A D12.A D13.A D14.A D22.2(CATHODE) D23.2(CATHODE) J2.A1_B12(P1) J2.B1_A12(P16) J2.G1(SH1) J2.G2(SH2) J2.G3(SH3) J2.G4(SH4) J7.4 J11.1(P1) J11.4(P4) J11.7(P7) J11.10(P10) J11.13(P13) J11.16(P16) J11.19(P19) J11.G1 J11.G2 J13.4(P4) J13.7(P7) J13.10(P10) J13.13(P13) J13.16(P16) J13.20(SH1) J13.21(SH2) J13.22(SH3) J13.23(SH4) J14.4(P4) J14.5(P5) J14.6(P6) J14.7(P7) J14.8(P8) J16.6(VSS) J16.10(SH1) J16.11(SH2) J16.12(SH3) J16.13(SH4) J17.3 J17.7(G1) J17.8(G2) J21.4 J21.7 J21.10 J21.13 J21.16 J21.19 J21.22 J21.23 J21.G1 J21.G2 J23.3 J24.1 J24.2 J24.7 J24.8 J24.13 J24.14 J24.22 J24.23 J24.32 J24.33 J24.42 J24.43 J24.52 J24.53 J24.59 J24.60 J24.65 J24.66 J24.71 J24.74 J24.98 J25.7 J25.8 J25.13 J25.14 J25.19 J25.20 J25.25 J25.26 J25.31 J25.32 J25.37 J25.38 J25.44 J25.50 J25.55 J25.56 J25.61 J25.62 J25.67 J25.68 J25.73 J25.74 J25.79 J25.80 J25.85 J25.86 J25.91 J25.92 J25.97 J25.98 J26.1(P1) J26.4(P4) J26.7(P7) J26.10(P10) J26.13(P13) J26.16(P16) J26.19(P19) J26.G1 J26.G2 J27.1 J28.1 J28.2 J28.7(G1) J28.8(G2) Q4.2(S) Q5.2(S) Q6.2(S) Q7.2(S) R87.1(A) R90.2(B) R91.2(B) R368.1(A) R371.1(A) R373.1(A) R3039.2 R3044.2 R3049.1 R3053.2 R3059.1 R3061.1 R3062.1 R3063.2(B) R3065.2 R3088.1(A) R3090.1(A) R3092.1(A) R3099.1(A) R3103.1(A) R3104.1(A) R3106.1(A) R3107.1(A) R3108.2(B) R3133.2 R3134.2 R3149.1(A) R3160.1 R3163.1(A) R3177.1 R3181.1 R3183.1 R3186.2(B) R3189.1(A) R3196.1 SW2.1 TP91.1(PIN1) TP99.1(PIN1) U3.12(DVSS1) U3.25(AVSS1) U3.33(AVSS2) U3.36(DVSS2) U5.2(GND) U6.4(GND) U12.7(GND) U18.15(VSS) U57.18(GND) U57.25(G) U60.2(GND) U501.2(GND1) U501.3(GND2) U580.5(GND) U597.15(AGND) U597.27(PGND1) U597.28(PGND2) U600.16(GND) U601.2(GND) U602.5(GND) U602.10(O\E\) Y2.2 Y2.4
VBAT: C2490.1 C2491.1 D18.2 J23.1 R3052.2(B) R3089.2(B) R3095.2(B) R3097.2(B) R3100.2(B) TP44.1(PIN1) U597.17(BAT)
VBAT_AD: C2525.1 R3052.1(A) R3053.1 R3154.1(A) U18.14(ADC_9)
VBAT_AD_C: J24.94 R3154.2(B)
VBUS: C68.1 C69.1 C85.2 C2484.1 C2485.1 C2486.1 C2495.1 C2496.1 F2.1(P1) FB2.1 FB8.2 FB9.2 FB10.1 FB13.2 L5.1 Q3.1(G) R124.1 R3086.1(A) R3101.1(A) R3137.1(A) R3168.2 R3169.2 TP30.1(PIN1) TP43.1(PIN1) U6.1(VIN) U597.3(SYS1) U597.20(SYS3) U597.29(SYS2) U600.13(VCC)
VBUSA: F2.2(P2) J14.1(P1) J28.5 J28.6 R3058.2 TP52.1(PIN1) U5.5(PW)
VDD_AMP: C20.1 FB2.2 TP57.1(PIN1) U12.6(VDD)
VDDA: C2474.1 C2479.1 FB7.2 U18.5(VDDA)
AMP_SHUTDOWN: J24.45 Q6.1(G) R3061.2 R3145.1 TP59.1(PIN1)
AU_IN: C2517.2 R127.1(A) R3184.2(B)
BL_EN: R88.2(B) R3197.1(A)
BOOST_EN: R3094.1 U18.11(SPI1_CLK) U597.24(MODE)
BT_NDIS: J24.91 TP78.1(PIN1)
CAM0_CN: J25.40 J26.8(P8)
CAM0_CP: J25.42 J26.9(P9)
CAM0_DN0: J25.28 J26.2(P2)
CAM0_DN1: J25.34 J26.5(P5)
CAM0_DP0: J25.30 J26.3(P3)
CAM0_DP1: J25.36 J26.6(P6)
CAM0_IO0: J24.27 J26.17(P17)
CAM0_IO1: J24.26 J26.18(P18)
CAM1_CN: J11.8(P8) J25.27
CAM1_CP: J11.9(P9) J25.29
CAM1_DN0: J11.2(P2) J25.15
CAM1_DN1: J11.5(P5) J25.21
CAM1_DN2: J11.11(P11) J25.33
CAM1_DN3: J11.14(P14) J25.39
CAM1_DP0: J11.3(P3) J25.17
CAM1_DP1: J11.6(P6) J25.23
CAM1_DP2: J11.12(P12) J25.35
CAM1_DP3: J11.15(P15) J25.41
CAM1_IO0: J11.17(P17) J24.34
CAM1_IO1: J11.18(P18) J24.54
CAM_GPIO: J24.97 TP79.1(PIN1)
CHARGE_EN: R3096.1 U18.12(SPI1_MISO) U597.25(EN)
CM_1V8: J21.3 J24.88 J24.90 R3057.1(A)
CM_3V3: C385.1 FB12.2 J11.22(P22) J21.1 J21.2 J24.84 J24.86 J26.22(P22) R15.2 R16.1 R17.1 R18.2 R370.1(A) R3157.1(A) R3165.2 R3166.2 R3167.1(A) U57.13(VDD)
CM_5V: C2505.1 FB10.2 J24.77 J24.79 J24.81 J24.83 J24.85 J24.87
DSI1_CN: J21.14 J25.87
DSI1_CP: J21.15 J25.89
DSI1_DN0: J21.11 J25.75
DSI1_DN1: J21.17 J25.81
DSI1_DN2: J21.20 J25.93
DSI1_DN3: J21.8 J25.94
DSI1_DP0: J21.12 J25.77
DSI1_DP1: J21.18 J25.83
DSI1_DP2: J21.21 J25.95
DSI1_DP3: J21.9 J25.96
E2P_CS: U3.4(CS) U580.1(CS)
E2P_DI: R3174.1(A) U580.4(DO)
E2P_DO: R3175.1(A) U580.3(DI)
E2P_SK: U3.3(SK) U580.2(SK)
EEPROM_WP: J24.20 TP84.1(PIN1)
GLOBAL_EN: J24.99 R3193.2(B) TP80.1(PIN1)
GPIO12: J24.31 R3197.2(B)
GPIO13: J24.28 Q7.1(G) R3196.2
GPIO14: J24.55 R3194.2(B)
GPIO15: J24.51 R3195.2(B)
GPIO16: J24.29 R3201.2(B)
GPIO25: J24.41 R3198.2(B)
GPIO_VEF(IN): J24.78 R3157.2(B)
GYRO_INT: J24.48 R3167.2(B) U57.12(INT)
HDMI1_SCL: J13.17(P17) J25.47 R3169.1
HDMI1_SDA: J13.18(P18) J25.45 R3168.1
HDMI_CEC: J25.49 Q3.2(S) R15.1
HDMI_CK_N: J13.14(P14) J25.66
HDMI_CK_P: J13.12(P12) J25.64
HDMI_D0_N: J13.11(P11) J25.60
HDMI_D0_P: J13.9(P9) J25.58
HDMI_D1_N: J13.8(P8) J25.54
HDMI_D1_P: J13.6(P6) J25.52
HDMI_D2_N: J13.5(P5) J25.48
HDMI_D2_P: J13.3(P3) J25.46
HDMI_HPD: J13.1(P1) Q4.1(G) R3062.2
HDMI_HPD_N: J25.43 Q4.3(D) R18.1
ID_SC: J24.35 TP90.1(PIN1)
ID_SD: J24.36 TP89.1(PIN1)
IN2SYS_EN: R3092.2(B) R3093.1(A) U18.13(SPI1_MOSI) U597.7(PWIN)
LCD_RST: J21.5 J24.30 R3057.2(B)
LED0: R3178.1 U3.11(LED0)
LEDR: R3179.1 U3.19(LEDR)
LOL: C2518.1 U3.30(LOL)
LOR: C2516.1 U3.32(LOR)
MCU_3V3: C2477.1 C2478.1 C2481.1 FB7.1 J7.1 R272.2 R3040.2 R3043.1 R3051.1 R3054.2 R3060.1 TP65.1(PIN1) TP98.1(PIN1) U18.16(VDD) U60.5(OUT)
MCU_IND: Q5.1(G) R3059.2 U18.9(ADC_3)
MCU_REV1: R3193.1(A) R3198.1(A) U18.6(PA0)
MCU_REV2: R3156.1(A) R3201.1(A) U18.7(PA1)
MCU_RST: C2523.1 R272.1 U18.4(NRST)
MICIN: R3199.1(A) R3200.1(A) U3.28(MICIN)
MODE: J24.40 R3176.1 R3177.2 U3.10(MODE)
MSEL: J24.50 R3182.1 R3183.2 U3.40(MSEL)
MUTEP: J24.49 U3.17(MUTEP)
MUTER: J24.37 U3.5(MUTER)
NRPIBOOT: J24.93 R3156.2(B)
OSC_IN: C2475.1 U18.2(OSC_IN) Y2.3
OSC_OUT: C2476.1 U18.3(OSC_OUT) Y2.1
PI_NLED_ACTIVITY: D1.2(CATHODE) J24.21
PWRSEL: J24.39 R3160.2 R3173.1 U3.6(PWRSEL)
REG1V8: C2515.1 U3.7(DREG18)
REG3V3: C2511.1 C2514.1 R3158.1(A) R3173.2 R3176.2 R3180.2 R3182.2 U3.8(DREG33) U580.8(VCC)
RUN_PG: J24.92 TP83.1(PIN1)
RXD0: R3041.1 R3195.1(A)
SCL0: J11.20(P20) J24.80 J26.20(P20) R16.2
SCL5: J24.38 R3165.1 U57.23(SCL)
SCL6: J24.47 R43.2(B)
SDA0: J11.21(P21) J24.82 J26.21(P21) R17.2
SDA5: J24.44 R3166.1 U57.24(SDA)
SDA6: J24.46 R42.2(B)
SDX_CLK: J24.57 R3141.1
SDX_CMD: J24.62 R3140.1
SDX_D0: J24.63 R3142.1
SDX_D1: J24.67 R3143.1
SDX_D2: J24.69 R3138.1
SDX_D3: J24.61 R3139.1
SDX_DET: J16.9(DET) J24.76 R3132.1
SEL: R3163.2(B) R3164.1(A) R3172.2(B) U602.2(SEL)
SWCLK: J7.3 R3044.1 TP63.1(PIN1) U18.20(SWCLK)
SWDIO: J7.2 R3043.2 TP62.1(PIN1) U18.19(SWDIO)
SWITCH: R3054.1 SW2.2 U18.10(SPI1_CS)
TEST: R3180.1 R3181.2 U3.20(TEST)
TOUCH_INT_B: J24.25 R120.2(B)
TP_RST: J24.24 R121.2(B)
TXD0: R3042.1 R3194.1(A)
USB1_DM: R122.1(A) U5.6(C21) U600.7(DM1)
USB1_DP: R123.1(A) U5.1(C11) U600.8(DP1)
USB2_DM: U3.44(USBDM) U600.5(DM2)
USB2_DP: U3.43(USBDP) U600.6(DP2)
USB3_DM: J28.4 U600.3(DM3)
USB3_DP: J28.3 U600.4(DP3)
USB5V_AD: C2526.1 R3064.1(A) R3065.1 R3155.1(A) U18.8(ADC_2)
USB5V_AD_C: J24.96 R3155.2(B)
USB_DN: J25.3 U602.4(D-)
USB_DP: J25.5 U602.3(D+)
USBH_DN: U600.10(DM) U602.8(HSD2-)
USBH_DP: U600.11(DP) U602.9(HSD2+)
USBOTG_ID: J25.1 Q7.3(D) R3172.1(A) TP94.1(PIN1)
USBS_DN: R3161.2(B) U601.4(C22) U602.6(HSD1-)
USBS_DP: R3162.2(B) U601.3(C12) U602.7(HSD1+)
VBIAS: R3190.1(A) U3.26(VBIAS)
VD33: C2497.1 C2512.1 U600.12(DCP) U600.14(V33)
VLED+: C76.1 C78.1 D10.C J21.29 J21.30 J21.31 TP33.1(PIN1)
VLED-: J21.25 J21.26 J21.27 R89.1(A) R90.1(A) R91.1(A) R3063.1(A)
VOLDN: J24.56 U3.47(VOLDN)
VOLUP: J24.58 U3.41(VOLUP)
WL_NDIS: J24.89 TP77.1(PIN1)
N1478133: D11.C J17.2 R42.1(A) R114.1
N1478157: D12.C J17.1 R43.1(A) R115.1
N1478281: C81.1 D14.C J17.4 R117.2 R121.1(A) TP28.1(PIN1)
N1478289: C82.1 D13.C J17.5 R118.2 R120.1(A) TP29.1(PIN1)
N12332208: J9.2 R125.1 TP60.1(PIN1) U12.5(VO1)
N12332215: J9.1 TP61.1(PIN1) U12.8(VO2)
N12333733: Q6.3(D) R124.2 U12.1(SD)
N12334307: C86.1 U12.2(BP) U12.3(IN+)
N12334479: R125.2 R126.1 U12.4(IN-)
N12334672: C87.2 R126.2
N12335205: C87.1 R127.2(B) TP58.1(PIN1)
N12373140: R368.2(B) U57.1(CLKIN)
N12374321: C383.1 R370.2(B) U57.8(VLOGIC)
N12375648: C384.1 U57.10(REGOUT)
N12375668: R371.2(B) U57.11(FSYNC)
N12378079: C386.2 U57.20(CPOUT)
N12396095: R3039.1 R3040.1 U18.1(BOOT0)
N12403489: R3042.2 U18.18(U1_RX)
N12403491: R3041.2 U18.17(U1_TX)
N12412618: C2480.1 D17.1 D18.1 TP64.1(PIN1) U60.1(IN) U60.3(EN)
N12412734: R3049.2 R3051.2 U60.4(FB)
N12455509: J13.15(P15) Q3.3(D)
N12499716: D19.2(CATHODE) Q5.3(D)
N12720539: D10.A L5.2 U6.3(SW)
N12720829: C73.1 R87.2(B) R88.1(A) R3066.2(B) U6.2(CTRL)
N12720857: R89.2(B) U6.6(FB)
N12720893: C74.1 U6.5(COMP)
N12836963: J13.19(P19) R3058.1
N12951060: J14.2(P2) R122.2(B) U5.4(C22)
N12951086: J14.3(P3) R123.2(B) U5.3(C12)
N12951166: R3086.2(B) R3088.2(B) U597.11(FB)
N12951176: C2483.2 R3087.1(A)
N12951178: R3087.2(B) U597.1(IB)
N12951234: L634.1 U597.2(SW1) U597.21(SW2)
N12951240: L634.2 R3089.1(A) U597.18(CSP)
N12951278: R3090.2(B) R3091.1(A) U597.9(REG)
N12951318: C2492.1 R3094.2 R3096.2 R3102.1(A) TP45.1(PIN1) U597.5(VCC)
N12951326: D20.2(CATHODE) U597.23(C\H\G\)
N12951328: D20.1(ANODE) R3095.1(A)
N12951350: R3097.1(A) U597.10(A\C\O\K\)
N12951358: R3098.2(B) R3101.2(B) R3103.2(B) R3137.2(B) U597.12(NTC)
N12951362: J23.2 R3098.1(A) TP47.1(PIN1)
N12951368: R3099.2(B) U597.26(FREQ)
N12951370: D21.2(CATHODE) U597.22(B\O\O\S\T\)
N12951372: D21.1(ANODE) R3100.1(A)
N12951392: R3102.2(B) R3104.2(B) U597.16(VB)
N12951398: C2493.1 U597.8(TMR)
N12951408: R3105.2(B) U597.6(ILIM)
N12951410: R3106.2(B) U597.13(ISET)
N12951412: R3107.2(B) U597.14(OLIM)
N12951420: R3105.1(A) R3108.1(A)
N12951470: F1.1(P1) J2.A4_B9(P3) J2.B4_A9(P14) TP41.1(PIN1)
N12951488: J2.A5(P6) R3133.1
N12951490: J2.B5(P12) R3134.1
N12951536: J16.1(DAT2) R3138.2
N12951538: J16.2(CD/DAT3) R3139.2
N12951540: J16.3(CMD) R3140.2
N12951542: J16.5(CLK) R3141.2
N12951544: J16.7(DAT0) R3142.2
N12951546: J16.8(DAT1) R3143.2
N13080452: R3174.2(B) U3.1(DR)
N13080482: FB13.1 U3.35(DVDD)
N13080512: C2503.1 C2504.1 FB8.1 U3.34(AVDD2)
N13080672: C2501.1 C2502.1 FB9.1 U3.29(AVDD1)
N13097468: C2507.1 U3.27(VREF)
N13098112: C2508.2 C2509.1 R3158.2(B) U501.1(VDD)
N13104223: C2510.1 C2524.2 U501.4(OUTPUT)
N13115240: D1.1(ANODE) R3.2
N13167489: J2.B8(P5) TP92.1(PIN1)
N13167505: J2.A8(P11) TP93.1(PIN1)
N13167521: J2.A6(P8) J2.B6(P10) R3162.1(A) U601.1(C11)
N13167621: J2.A7(P9) J2.B7(P7) R3161.1(A) U601.6(C21)
N13191587: R3149.2(B) U600.9(REF)
N13218298: R3175.2(B) U3.2(DW)
N13235636: TP95.1(PIN1) U3.42(PDSW)
N13236221: C2513.1 U3.39(AREG36)
N13242775: C2516.2 R3185.1(A)
N13242801: R3184.1(A) R3185.2(B) R3186.1(A)
N13245751: C2519.1 R3188.2(B) TP97.1(PIN1)
N13245789: R3187.2(B) R3188.1(A) R3189.2(B)
N13245825: C2518.2 R3187.1(A)
N13254228: C2520.1 R3190.2(B) R3192.1(A)
N13255610: C2521.2 R3191.1(A)
N13255658: C2522.1 J27.2 R3191.2(B) R3192.2(B)
N13279315: C2524.1 R3199.2(B)
N13279395: C2521.1 R3200.2(B)
N13284349: TP100.1(PIN1) U600.1(DM4)
N13284361: TP101.1(PIN1) U600.2(DP4)
N123465088: R373.2(B) U57.9(AD0)
N124996560: D19.1(ANODE) R3060.2
N132243780: D22.1(ANODE) R3178.2
N132252170: D23.1(ANODE) R3179.2
N1308043429: TP81.1(PIN1) U3.31(LOBS)

Pads without a net: J13 2; J21 6 24 28; J24 3 4 5 6 9 10 11 12 15 16 17 18 19 64 68 70 72 73 75 95 100; J25 2 4 6 9 10 11 12 16 18 22 24 51 53 57 59 63 65 69 70 71 72 76 78 82 84 88 90 99 100; J26 11 12 14 15; U3 9 13 14 15 16 18 21 22 23 24 37 38 45 46 48; U57 2 3 4 5 6 7 14 15 16 17 19 21 22; U580 6 7; U600 15

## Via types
v1: diameter 0.508, hole 0.254, TOP to BOTTOM, 1146 vias

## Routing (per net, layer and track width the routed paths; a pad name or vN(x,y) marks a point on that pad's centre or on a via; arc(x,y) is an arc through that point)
3V3: length 59
  TOP w0.254: R3145.2 64.11,100.49 64.39,100.2 65.41,100.2 65.66,99.95 65.66,99.44 v1(66.04,99.06)
  TOP w0.305: R114.2 v1(73.66,65.02) ; U602.1 19.03,72.63 19.56,73.15 C17.2 ; R118.1 v1(73.79,57.66) ; v1(78.11,66.85) R115.2 ; R3066.1 v1(43.85,17.02) ; R117.1 v1(73.66,62.36)
  TOP w0.381: R3.1 v1(63.37,79.88) 55.63,72.14 v1(51.94,72.14) ; C17.2 v1(20.48,73.63)
  BOTTOM w0.381: v1(51.94,72.14) 21.97,72.14 v1(20.48,73.63)
  vias: v1(34.04,8.26) v1(35.05,8.26) v1(67.56,92.08) v1(68.2,91.31) v1(68.83,92.08) v1(80.77,56.13) v1(80.77,54.99) v1(81.92,56.13) v1(81.92,54.99)
3V3_SD: length 33.8
  TOP w0.381: R3132.2 v1(19.94,17.14) ; R3153.2 30.51,5.05 C24.1 v1(29.21,5.08) 27.31,6.99 22.23,6.99 20.39,5.15 J16.4
  L03 w0.381: v1(19.94,17.14) 20.7,16.38 20.7,10.03 22.1,8.64 25.66,8.64 v1(29.21,5.08)
5V_IN: length 18.1
  TOP w0.305: R3091.2 v1(75.44,10.54) ; v1(72.42,9.14) R3093.2
  TOP w0.381: R3164.2 16.26,74.93 v1(14.99,73.66) ; U601.5 v1(10.5,69.98)
  L03 w0.305: v1(75.44,10.54) 73.82,10.54 v1(72.42,9.14) 72.42,7.4 69.98,4.95 67.18,4.95 v1(66.58,4.36)
  vias: v1(13.08,60.33) v1(13.08,59.05) v1(13.84,59.69) v1(14.61,60.33) v1(14.61,59.05) v1(15.37,59.69) v1(64.55,4.36) v1(64.55,3.56) v1(65.57,4.36) v1(65.57,3.56) v1(66.58,3.56) v1(83.06,26.29) v1(83.06,25.15) v1(84.07,26.29) v1(84.07,25.15)
GND: length 598
  TOP w0.203: J24.42 56.7,87.44 v1(57.15,87) ; v1(24.38,87.12) 24.86,86.64 J25.37 ; v1(60.96,89.53) 60.65,89.84 J24.53 ; v1(23.5,95.25) 23.5,95.24 23.29,95.04 J25.80 ; v1(55.24,92.08) 55.41,92.24 J24.66 ; J25.62 v1(23.24,91.44) ; J24.43 58.76,87.84 58.42,87.5 v1(58.42,87) ; v1(20.95,85.6) 21.11,85.44 J25.32 ; v1(57.15,84.45) 57.15,84.96 56.67,85.44 J24.32 ; J25.79 26.5,95.04 v1(26.67,94.87) ; J25.55 26.23,90.24 v1(26.42,90.42) ; v1(57.15,90.81) 56.91,91.04 J24.60 ; v1(55.24,93.34) 55.74,93.84 J24.74 ; J24.52 57.06,89.44 v1(57.15,89.53) ; v1(58.42,83.82) 58.67,83.82 58.7,83.84 J24.23 ; v1(24.38,81.53) 24.69,81.84 J25.13 ; J25.8 22.86,80.64 23.11,80.9 v1(23.11,81.03) ; J13.7 7.42,84.15 v1(7.49,84.07) ; J25.20 22.91,83.04 23.11,82.84 v1(23.11,82.55) ; J25.14 v1(21.46,81.84) ; J25.74 23,93.84 v1(23.24,93.6) ; J25.56 v1(23.24,90.24) ; J13.10 3.64,84.75 v1(3.56,84.84) ; J13.13 6.99,85.35 7.37,85.72 v1(7.49,85.72) ; v1(20.95,84.07) 21.12,84.24 J25.26 ; J25.7 v1(24.38,80.64) ; J25.85 v1(26.52,96.24) ; v1(20.95,86.49) 21.11,86.64 J25.38 ; U597.28 64.03,14.37 v1(63.91,14.48) 64.2,14.77 U597.27 ; v1(58.42,92.08) 58.59,92.24 J24.65 ; J25.92 21.24,97.44 v1(21.08,97.28) ; v1(3.68,83.44) 3.79,83.55 J13.4 ; U57.18 71.51,87.85 v1(71.74,87.63) ; J13.16 4.22,85.95 3.91,86.26 v1(3.56,86.26) ; v1(58.42,85.72) 58.54,85.84 J24.33 ; v1(58.42,93.34) 58.52,93.44 J24.71 ; J25.44 22.94,87.84 v1(23.24,88.14) ; v1(24.38,83.95) 24.68,84.24 J25.25 ; v1(24.38,82.55) 24.88,83.04 J25.19 ; J24.22 55.5,83.44 v1(55.24,83.19) ; v1(23.5,96.01) 23.27,96.24 J25.86 ; J25.91 v1(24.29,97.44) ; v1(24.38,84.96) 24.86,85.44 J25.31 ; J24.7 v1(58.42,80.64) ; J24.1 58.49,79.44 v1(58.42,79.38) ; v1(26.54,93.47) 26.29,93.47 25.92,93.84 J25.73 ; J24.2 55.31,79.44 v1(55.24,79.38) ; J24.8 v1(55.25,80.64) ; J25.67 v1(26.49,92.64) ; v1(24.26,98.64) J25.97 ; J25.68 v1(23.18,92.64) ; J25.50 v1(23.24,89.04) ; v1(57.15,98.42) 56.93,98.64 J24.98 ; J25.61 v1(26.42,91.44) ; v1(55.24,81.92) 55.32,81.84 J24.14 ; v1(60.96,90.81) 60.72,91.04 J24.59 ; v1(21.08,98.81) 21.25,98.64 J25.98 ; v1(60.96,81.92) 60.89,81.84 J24.13
  TOP w0.254: U3.33 33.35,29.03 v1(33.78,29.46) ; C2492.2 71.69,6.83 ; C2492.2 71.69,5.87 ; C2492.2 72.17,6.35 ; v1(19.05,65.79) 19.03,65.8 U602.10 ; v1(68.51,18.21) 68.51,18.06 68.11,17.66 U597.15 v1(69.24,17.27) ; 74.45,7.26 R3108.2 ; R3108.2 74.45,8.23 ; R3108.2 74.93,7.75 ; 6.25,14.11 C2508.1 6.73,13.63 ; 28.3,53.5 R3149.1 27.81,53.98 ; v1(87,42.2) J21.G2 88.02,42.2 v1(89.03,42.2) ; C2509.2 5.94,14.11 ; C2509.2 4.98,14.11 ; C2509.2 5.46,13.63 ; 11.39,72.05 R3133.2 10.91,72.54 ; v1(84.58,61.25) J17.3 ; 15.37,77.47 R3196.1 15.85,77.95 ; 74.45,8.66 R3092.1 74.93,9.14 ; U3.36 v1(34.85,29.41) ; U3.25 v1(29.35,29.2) ; R87.1 45.73,16.29 ; R87.1 44.76,16.29 ; R87.1 45.25,16.77 ; v1(63.91,14.48) v1(63.15,14.48) ; U3.12 v1(29.35,35.19)
  TOP w0.305: C2511.2 v1(30.61,40.77) ; J11.4 83.52,82.75 v1(83.47,82.7) ; J11.10 83.52,79.75 v1(83.47,79.7) ; D12.A v1(78.11,65.07) ; R371.1 v1(78.23,89.15) ; v1(83.57,75.18) 83.63,75.25 J11.19 ; Q5.2 66.98,36.58 66.77,36.8 R3059.1 v1(66.28,35.43) ; v1(71.75,110.24) 71.77,110.22 J26.10 ; v1(68.77,110.24) 68.77,110.24 J26.4 ; J11.1 83.52,84.25 v1(83.47,84.2) ; C2476.2 v1(61.23,33.65) 61.47,33.65 61.85,33.27 61.85,32.51 61.98,32.38 v1(61.98,30.99) 61.98,30.98 61.68,30.67 Y2.4 60.84,29.9 60.53,29.59 v1(60.45,29.59) v1(58.93,29.59) 57.71,29.59 v1(57.33,29.97) v1(57.33,30.99) v1(57.33,32.27) 57.63,32.57 Y2.2 58.54,33.41 58.12,33.83 C2475.2 v1(57.39,34.41) ; v1(89.15,39.5) 88.95,39.7 J21.7 ; v1(72.44,10.44) 72.34,10.54 C2493.2 ; C80.2 v1(78.11,57.15) ; v1(83.47,81.2) 83.52,81.25 J11.7 ; R3183.1 41.15,29.97 v1(41.27,29.84) ; R3106.1 v1(72.42,16.89) ; J21.13 89.08,37.9 v1(89.15,37.97) ; C2502.2 v1(28.96,25.4) ; v1(63.14,48.51) 63.14,48.25 C2478.2 64.41,48.51 v1(64.53,48.51) 64.53,48.51 C2481.2 65.93,48.38 v1(66.18,48.38) ; v1(84.23,34.67) 84.77,35.2 85.41,35.2 J21.22 ; C2517.1 v1(37.59,18.92) ; J21.16 84.63,37 84.23,36.61 v1(84.23,36.2) ; v1(73.28,110.24) 73.27,110.22 J26.13 ; v1(29.46,6.6) C24.2 v1(31.37,6.6) ; R373.1 v1(78.23,86.61) ; J21.10 84.77,38.8 v1(84.45,39.12) ; v1(89.15,34.9) 89.15,34.9 J21.23 ; v1(25.02,25.27) C2507.2 ; C2495.2 v1(27.81,49.28) ; J11.13 83.62,78.25 v1(83.6,78.23) ; R3039.2 v1(55.93,37.3) ; R3181.1 v1(23.62,30.86) ; J26.19 v1(76.27,110.24) ; J21.G1 88.98,31.8 v1(89.03,31.75) ; C383.2 v1(78.23,85.34) ; C2523.2 64.55,32.43 v1(65.01,32.89) C2479.2 ; D11.A v1(78.11,63.04) ; TP99.1 52.35,61.9 J7.4 52.35,52.81 52.48,52.68 R3044.2 ; Q4.2 13.07,87.88 v1(13.21,88.01) ; C2477.2 61.99,48.12 v1(61.98,48.13) ; C82.2 v1(73.66,59.18) ; R368.1 v1(73.15,82.93) ; D14.A 78.15,61.01 v1(78.11,60.96) ; C2501.2 v1(28.19,23.88) ; R3186.2 v1(36.83,20.32) ; v1(17.27,70.23) 17.03,70.47 U602.5 ; R3088.1 72.17,13.81 v1(72.17,14.1) R3103.1 ; v1(89.15,36.1) 89.15,36.1 J21.19 ; R3062.1 v1(9.88,90.07) ; J21.4 84.8,40.6 v1(84.45,40.26) ; R3090.1 v1(75.44,11.94) ; R3177.1 v1(28.07,40.77) ; C2520.2 v1(12.32,22.99) ; D13.A v1(78.11,58.97) ; D22.2 v1(25.27,37.47) ; v1(61.61,41.14) 62.05,41.58 U18.15 ; C2514.2 v1(29.34,40.77) ; v1(67.56,38.73) C2526.2 ; C2474.2 63.74,33.14 v1(63.99,32.89) ; C81.2 v1(73.66,60.83) ; R3065.2 v1(66.31,38.73) ; R3134.2 v1(11.77,63.67) ; C2525.2 v1(67.56,43.31) ; J26.1 v1(67.27,110.24) ; R3104.1 v1(72.93,20.48) ; C2515.2 v1(31.88,40.77) ; C2504.2 v1(36.71,22.86) ; v1(66.31,43.31) R3053.2 ; v1(68.72,48.13) 68.36,48.5 R3049.1 ; C386.1 v1(69.72,86.58) ; J26.16 v1(74.77,110.24) ; C17.1 v1(19.56,75.31) ; J26.7 v1(70.27,110.24) ; C385.2 v1(72.52,90.17) ; C384.2 v1(78.23,87.88) ; R3160.1 v1(33.15,40.77) ; R3107.1 v1(72.42,18.29) ; J11.16 v1(83.57,76.75) ; C2503.2 v1(36.45,25.27)
  TOP w0.381: C2512.2 v1(27.81,44.2) 28.32,43.69 U600.16 ; J2.B1_A12 6.67,64.05 6.29,63.67 J2.G2 ; J2.A1_B12 v1(7.87,71.19) ; 16.13,49.15 15.68,49.59 v1(15.68,49.75) ; 16.13,49.15 U5.2 ; 16.13,49.15 16.51,49.53 v1(16.51,49.78) ; U601.2 v1(10.5,65.75) ; C2519.2 30.48,19.05 v1(30.48,20.32) R3189.1 ; v1(8.21,16.55) C2510.2 v1(7.11,17.52) ; TP91.1 77.63,12.1 J23.3 ; R3044.2 v1(53.34,51.82) ; R3163.1 v1(16.51,73.66)
  TOP w0.4: 1.22,15.92 U501.3 ; U501.3 1.85,16.55 ; U501.3 1.22,17.18 ; 1.22,14.22 U501.2 ; U501.2 1.85,14.85 ; U501.2 1.22,15.48
  TOP w0.405: 74.68,60.2 C81.2 74.68,61.47 ; 50.58,14.35 R91.2 ; R91.2 51.21,14.96 ; R91.2 51.85,14.35 ; C2522.2 7.11,22.49 ; C2522.2 7.75,21.88 ; C2522.2 6.48,21.88 ; C68.2 31.5,11.69 ; C68.2 30.86,11.08 ; C68.2 30.23,11.69 ; C2513.2 41.76,28.57 ; C2513.2 41.15,29.21 ; C2513.2 41.15,27.94 ; 52.23,14.35 R90.2 ; R90.2 52.87,14.96 ; R90.2 53.5,14.35 ; 74.68,58.55 C82.2 74.68,59.82 ; 47.38,13.84 C73.2 46.77,14.48 ; 68.87,97.69 C86.2 ; C86.2 68.28,98.3 ; C86.2 68.87,98.91 ; 79.41,57.79 C80.2 79.41,56.51 ; 82.84,36.21 R3063.2 82.2,35.6
  TOP w0.474: D23.2 21.04,33.09 ; D23.2 21.04,31.68 ; D23.2 20.37,32.38
  TOP w0.477: 47.69,10.35 U6.4 46.77,9.82
  TOP w0.508: J14.5 10.32,53.32 v1(10.32,52.07) ; U580.5 v1(42.8,36.45) ; v1(68.72,46.86) 68.85,46.73 U60.2 v1(71.25,46.73) 71.39,46.73 71.49,46.63 C2480.2
  TOP w0.61: 23.31,48.01 C2496.2 24.02,47.17 ; 79.49,24.03 C2490.2 ; C2490.2 79.49,25.76 ; C2490.2 80.22,24.89 ; 23.31,45.59 C2497.2 24.02,46.43 ; 79.49,21.87 C2491.2 ; C2491.2 80.22,22.73 ; C2491.2 79.49,23.6 ; 51.93,10.79 C74.2 51.2,9.93 ; 49.94,6.71 C78.2 50.8,7.45 ; 32.77,10.58 C69.2 ; C69.2 33.63,11.32 ; C69.2 31.9,11.32 ; 60.5,7.01 C2485.2 ; C2485.2 59.76,7.87 ; C2485.2 60.5,8.74 ; 59.76,9.91 C2486.2 ; C2486.2 60.5,9.04 ; C2486.2 60.5,10.77
  TOP w0.635: 85.51,58.05 J17.7 ; J17.7 86.74,58.68 ; J17.7 86.74,57.43 ; J17.7 87.97,58.05 ; 11,55.5 J14.5 12.5,54 ; C76.2 47.79,8.4 ; C76.2 49.36,7.37 ; C76.2 46.21,7.37 ; 35.81,9.13 C85.1 ; C85.1 35.81,11.19 ; C85.1 34.24,10.16 ; C85.1 37.39,10.16 ; 16.13,1.63 J16.11 14.27,1.63 ; 16.8,13.85 J16.12 15.92,14.78 ; J17.8 86.74,64.58 ; J17.8 87.97,63.95 ; J17.8 85.51,63.95 ; J17.8 86.74,63.33 ; 59.49,4.56 C2484.2 ; C2484.2 58.65,5.59 ; C2484.2 60.33,5.59 ; C2484.2 59.49,6.62 ; J14.8 4.44,39.45 ; J14.8 2.91,38.22 ; J14.8 1.38,39.45 ; J16.13 22.5,15.71 ; J16.13 23.38,14.78 ; J16.13 22.5,13.85 ; J16.13 21.62,14.78 ; 65.51,94.75 C2505.2 ; C2505.2 65.51,96.76 ; C2505.2 66.32,95.76 ; 18.35,60.48 C2.2 ; C2.2 17.51,61.51 ; C2.2 18.35,62.54 ; J14.7 2.91,56.68 ; J14.7 4.44,55.45 ; J14.7 1.38,55.45 ; 77.99,102.1 C20.2 ; C20.2 77.99,104.15 ; C20.2 78.83,103.12 ; C20.2 77.15,103.12
  TOP w0.64: J26.G2 66.2,112.38 ; J26.G2 64.94,112.38 ; J26.G2 65.57,111.15 ; J26.G2 65.57,113.6 ; 87.58,85.32 J11.G2 ; J11.G2 87.58,86.58 ; J11.G2 88.81,85.95 ; J11.G2 86.36,85.95 ; 79.47,111.15 J26.G1 ; J26.G1 79.47,113.6 ; J26.G1 80.1,112.38 ; J26.G1 78.84,112.38 ; J28.8 42.86,50.42 ; J28.8 42.86,49.21 ; J28.8 41.66,49.81 ; J28.8 44.07,49.81 ; J28.7 42.86,44.52 ; J28.7 44.07,43.91 ; J28.7 41.66,43.91 ; J11.G1 88.81,72.05 ; J11.G1 86.36,72.05 ; J11.G1 87.58,71.42 ; J11.G1 87.58,72.68
  TOP w0.787: J14.4 12.1,44.94 ; J14.4 11.11,43.95 ; J14.4 12.1,42.96 ; J14.4 13.09,43.95 ; J2.G4 1.93,64.4 ; J2.G4 2.96,63.67 ; J2.G4 1.93,62.94 ; 1.36,86.87 J13.23 ; J13.23 2.87,87.85 ; J13.23 1.36,88.83 ; J14.6 11,42.4 ; J14.6 11,39.4 ; J14.6 12.5,40.9 ; 3.22,81.65 J13.22 ; J13.22 4.72,80.67 ; J13.22 6.23,81.65 ; 4.83,72.31 J2.G1 6.11,73.04 ; J2.G3 2.96,72.31 ; J2.G3 1.93,73.04 ; J2.G3 1.93,71.58 ; J13.21 4.72,88.83 ; J13.21 6.23,87.85 ; J13.21 3.22,87.85 ; SW2.1 4.45,97.93 ; SW2.1 4.45,96.07 ; SW2.1 5.28,97 ; SW2.1 3.62,97 ; 1.36,80.67 J13.20 ; J13.20 2.87,81.65 ; J13.20 1.36,82.63
  GND02 w0.635: 11,52.53 J14.5 ; J14.5 11,55.47 ; J14.5 12.47,54
  GND02 w0.813: J13.23 1.36,88.8 ; J13.23 1.36,86.9 ; J13.23 2.84,87.85 ; 4.45,96.1 SW2.1 ; SW2.1 5.25,97 ; SW2.1 4.45,97.9 ; SW2.1 3.65,97 ; 11.13,43.95 J14.4 ; J14.4 12.1,42.98 ; J14.4 13.07,43.95 ; J14.4 12.1,44.92 ; 4.72,80.7 J13.22 ; J13.22 4.72,82.6 ; J13.22 6.2,81.65 ; J13.22 3.25,81.65 ; 4.72,86.9 J13.21 ; J13.21 6.2,87.85 ; J13.21 4.72,88.8 ; J13.21 3.25,87.85 ; 4.86,72.31 J2.G1 ; J2.G1 6.11,73.01 ; J2.G1 7.36,72.31 ; 4.86,63.67 J2.G2 ; J2.G2 7.36,63.67 ; J2.G2 6.11,62.97 ; 0.93,63.67 J2.G4 ; J2.G4 1.93,62.97 ; J2.G4 1.93,64.37 ; J2.G4 2.93,63.67 ; J14.6 11,42.37 ; J14.6 12.47,40.9 ; J14.6 11,39.43 ; 1.93,71.61 J2.G3 ; J2.G3 1.93,73.01 ; J2.G3 0.93,72.31 ; J2.G3 2.93,72.31 ; J13.20 2.84,81.65 ; J13.20 1.36,80.7 ; J13.20 1.36,82.6
  L03 w0.635: 11,52.53 J14.5 11,55.47
  L03 w0.78: 0.93,72.31 J2.G3 ; J2.G3 2.93,72.31 ; J2.G3 1.93,71.61 ; J2.G3 1.93,73.01 ; 4.86,63.67 J2.G2 ; J2.G2 7.36,63.67 ; J2.G2 6.11,62.97 ; 4.86,72.31 J2.G1 ; J2.G1 7.36,72.31 ; J2.G1 6.11,73.01 ; 0.93,63.67 J2.G4 ; J2.G4 1.93,64.37 ; J2.G4 2.93,63.67 ; J2.G4 1.93,62.97 ; J13.23 1.36,88.8 ; J13.23 2.84,87.85 ; J13.23 1.36,86.9 ; 4.72,80.7 J13.22 ; J13.22 3.25,81.65 ; J13.22 6.2,81.65 ; J13.22 4.72,82.6 ; SW2.1 5.25,97 ; SW2.1 4.45,97.9 ; SW2.1 3.65,97 ; SW2.1 4.45,96.1 ; 1.36,80.7 J13.20 ; J13.20 1.36,82.6 ; J13.20 2.84,81.65 ; J14.4 12.1,44.92 ; J14.4 13.07,43.95 ; J14.4 11.13,43.95 ; J14.4 12.1,42.98 ; 4.72,88.8 J13.21 3.25,87.85 ; J14.6 11,42.37 ; J14.6 11,39.43 ; J14.6 12.47,40.9
  L04 w0.635: 11,52.53 J14.5 ; J14.5 12.47,54 ; J14.5 11,55.47
  L04 w0.78: J13.23 1.36,88.8 ; J13.23 2.84,87.85 ; J13.23 1.36,86.9 ; 1.36,80.7 J13.20 ; J13.20 2.84,81.65 ; J13.20 1.36,82.6 ; J2.G1 7.36,72.31 ; J2.G1 6.11,73.01 ; J2.G1 4.86,72.31 ; J14.4 12.1,44.92 ; J14.4 13.07,43.95 ; J14.4 11.13,43.95 ; J14.4 12.1,42.98 ; 0.93,72.31 J2.G3 ; J2.G3 2.93,72.31 ; J2.G3 1.93,71.61 ; J2.G3 1.93,73.01 ; SW2.1 4.45,97.9 ; SW2.1 3.65,97 ; SW2.1 5.25,97 ; SW2.1 4.45,96.1 ; 3.25,81.65 J13.22 ; J13.22 6.2,81.65 ; J13.22 4.72,82.6 ; J13.22 4.72,80.7 ; 4.86,63.67 J2.G2 ; J2.G2 7.36,63.67 ; J2.G2 6.11,62.97 ; J13.21 6.2,87.85 ; J13.21 4.72,88.8 ; J13.21 3.25,87.85 ; 11,39.43 J14.6 ; J14.6 12.47,40.9 ; J14.6 11,42.37 ; J2.G4 2.93,63.67 ; J2.G4 0.93,63.67 ; J2.G4 1.93,62.97 ; J2.G4 1.93,64.37
  GND05 w0.635: 11,52.53 J14.5 ; J14.5 12.47,54 ; J14.5 11,55.47
  GND05 w0.813: 0.93,72.31 J2.G3 ; J2.G3 1.93,73.01 ; J2.G3 2.93,72.31 ; J2.G3 1.93,71.61 ; SW2.1 4.45,97.9 ; SW2.1 5.25,97 ; SW2.1 3.65,97 ; SW2.1 4.45,96.1 ; 6.11,62.97 J2.G2 ; J2.G2 4.86,63.67 ; J2.G2 7.36,63.67 ; 1.36,80.7 J13.20 ; J13.20 2.84,81.65 ; J13.20 1.36,82.6 ; 12.1,42.98 J14.4 ; J14.4 13.07,43.95 ; J14.4 12.1,44.92 ; J14.4 11.13,43.95 ; 4.72,80.7 J13.22 ; J13.22 3.25,81.65 ; J13.22 6.2,81.65 ; J13.22 4.72,82.6 ; J2.G4 2.93,63.67 ; J2.G4 0.93,63.67 ; J2.G4 1.93,62.97 ; J2.G4 1.93,64.37 ; 4.86,72.31 J2.G1 ; J2.G1 7.36,72.31 ; J2.G1 6.11,73.01 ; 1.36,86.9 J13.23 ; J13.23 2.84,87.85 ; J13.23 1.36,88.8 ; J13.21 6.2,87.85 ; J13.21 4.72,88.8 ; J13.21 3.25,87.85 ; J13.21 4.72,86.9 ; 11,39.43 J14.6 ; J14.6 11,42.37 ; J14.6 12.47,40.9
  BOTTOM w0.635: J14.5 12.5,54 ; J14.5 11,52.5 ; J14.5 11,55.5
  BOTTOM w0.787: 3.62,97 SW2.1 ; SW2.1 4.45,96.07 ; SW2.1 4.45,97.93 ; SW2.1 5.28,97 ; J14.6 11,42.4 ; J14.6 12.5,40.9 ; J14.6 11,39.4 ; 4.72,80.67 J13.22 ; J13.22 6.23,81.65 ; J13.22 4.72,82.63 ; J13.22 3.22,81.65 ; J2.G4 2.96,63.67 ; J2.G4 1.93,62.94 ; J2.G4 1.93,64.4 ; J13.23 2.87,87.85 ; J13.23 1.36,88.83 ; J13.23 1.36,86.87 ; J2.G1 6.11,73.04 ; J2.G1 7.39,72.31 ; J2.G1 4.83,72.31 ; 1.93,71.58 J2.G3 ; J2.G3 1.93,73.04 ; J2.G3 2.96,72.31 ; J14.4 12.1,44.94 ; J14.4 13.09,43.95 ; J14.4 11.11,43.95 ; J14.4 12.1,42.96 ; J13.20 2.87,81.65 ; J13.20 1.36,80.67 ; J13.20 1.36,82.63 ; 6.11,62.94 J2.G2 ; J2.G2 7.39,63.67 ; J2.G2 4.83,63.67 ; J13.21 4.72,88.83 ; J13.21 6.23,87.85 ; J13.21 4.72,86.87 ; J13.21 3.22,87.85
  vias: v1(0.89,61.59) v1(0.89,59.69) v1(0.89,57.78) v1(0.89,55.88) v1(1.14,17.73) v1(1.27,90.17) v1(1.27,11.43) v1(1.43,86.36) v1(1.43,83.82) v1(1.43,80.01) v1(1.43,77.47) v1(1.43,74.93) v1(1.43,71.12) v1(1.43,68.58) v1(1.43,66.04) v1(1.43,36.83) v1(1.43,34.29) v1(1.43,31.75) v1(1.43,29.21) v1(1.43,26.67) v1(1.43,13.97) v1(1.43,8.89) v1(2.54,61.59) v1(2.54,59.69) v1(2.54,57.78) v1(2.79,70.1) v1(2.79,67.44) v1(3.05,65.41) v1(3.17,99.06) v1(3.17,17.78) v1(3.81,106.68) v1(3.81,104.14) v1(3.81,95.25) v1(3.81,92.71) v1(3.81,90.17) v1(3.94,31.75) v1(3.94,26.67) v1(3.94,24.77) v1(3.94,22.99) v1(3.97,80.01) v1(3.97,77.47) v1(3.97,74.93) v1(3.97,71.12) v1(3.97,36.83) v1(3.97,34.29) v1(3.97,29.21) v1(3.97,13.97) v1(3.97,8.89) v1(4.45,61.59) v1(4.45,59.69) v1(4.45,57.78) v1(4.45,19.05) v1(4.45,17.78) v1(5.08,100.33) v1(5.46,69.47) v1(5.46,67.7) v1(5.84,90.17) v1(6.35,106.68) v1(6.35,104.14) v1(6.35,97.79) v1(6.35,95.25) v1(6.35,92.71) v1(6.35,61.59) v1(6.35,59.69) v1(6.35,57.78) v1(6.35,55.88) v1(6.35,19.05) v1(6.51,80.01) v1(6.51,77.47) v1(6.51,74.93) v1(6.51,39.37) v1(6.51,36.83) v1(6.51,34.29) v1(6.48,31.75) v1(6.51,29.21) v1(6.48,26.67) v1(6.48,24.77) v1(6.48,22.99) v1(6.51,11.43) v1(6.51,8.89) v1(7.49,82.68) v1(7.62,74.3) v1(8.26,97.79) v1(8.26,95.25) v1(8.26,92.71) v1(8.26,59.69) v1(8.26,57.78) v1(8.26,55.88) v1(8.76,68.46) v1(8.76,66.81) v1(8.89,113.79) v1(8.89,111.76) v1(8.89,109.22) v1(8.89,106.68) v1(8.89,104.14) v1(8.89,19.05) v1(8.89,17.14) v1(8.89,15.24) v1(9.05,74.93) v1(9.05,39.37) v1(9.05,36.83) v1(9.05,34.29) v1(9.05,31.75) v1(9.05,29.21) v1(9.05,26.67) v1(9.05,24.77) v1(9.05,22.99) v1(9.05,11.43) v1(9.05,6.35) v1(9.05,3.81) v1(9.05,1.27) v1(10.16,59.69) v1(10.16,57.78) v1(10.16,55.88) v1(10.16,43.05) v1(10.32,49.53) v1(10.32,46.99) v1(10.32,44.45) v1(10.79,19.05) v1(10.79,17.14) v1(10.79,15.24) v1(11.43,113.79) v1(11.43,111.76) v1(11.43,109.22) v1(11.43,106.68) v1(11.43,104.14) v1(11.43,97.79) v1(11.43,95.25) v1(11.43,92.71) v1(11.43,74.93) v1(11.43,11.43) v1(11.59,36.7) v1(11.59,34.16) v1(11.56,31.62) v1(11.59,29.08) v1(11.56,26.54) v1(11.56,24.64) v1(11.59,8.89) v1(11.59,6.35) v1(11.59,3.81) v1(11.59,1.27) v1(12.06,73.66) v1(12.06,72.39) v1(12.06,57.78) v1(12.06,55.88) v1(12.7,19.05) v1(12.7,17.14) v1(12.7,15.24) v1(13.34,72.39) v1(13.34,11.43) v1(13.34,8.89) v1(13.5,6.35) v1(13.5,3.81) v1(13.5,1.27) v1(13.59,45.59) v1(13.97,113.79) v1(13.97,111.76) v1(13.97,109.22) v1(13.97,106.68) v1(13.97,43.81) v1(13.97,41.91) v1(13.97,39.37) v1(14.13,36.7) v1(14.13,34.16) v1(14.13,31.62) v1(14.13,29.08) v1(14.13,26.54) v1(14.13,24.64) v1(14.48,45.59) v1(15.24,77.09) v1(15.88,88.14) v1(15.88,12.7) v1(16.51,113.79) v1(16.51,111.76) v1(16.51,109.22) v1(16.51,77.09) v1(16.64,96.01) v1(16.64,94.61) v1(16.64,93.22) v1(16.64,2.54) v1(16.67,1.27) v1(17.53,88.14) v1(17.78,79.38) v1(17.78,12.7) v1(17.78,10.79) v1(17.91,86.61) v1(17.91,82.93) v1(17.91,2.54) v1(17.94,1.27) v1(18.03,94.61) v1(18.16,93.22) v1(18.16,91.57) v1(18.29,59.82) v1(18.29,58.55) v1(18.41,63.25) v1(18.8,88.9) v1(18.92,83.95) v1(19.05,113.79) v1(19.05,111.76) v1(19.05,109.22) v1(19.18,1.27) v1(19.43,86.61) v1(19.68,14.61) v1(19.68,12.7) v1(19.68,10.79) v1(19.94,6.99) v1(20.19,90.42) v1(20.32,40.01) v1(20.32,38.1) v1(20.32,36.2) v1(20.32,34.29) v1(20.32,31.11) v1(20.32,29.34) v1(20.32,27.94) v1(20.83,75.56) v1(20.83,7.75) v1(20.95,71.75) v1(21.59,12.7) v1(21.59,10.79) v1(22.23,73.66) v1(22.23,66.67) v1(22.61,48.26) v1(22.61,46.99) v1(22.61,45.47) v1(22.86,77.47) v1(23.24,84.84) v1(23.24,83.95) v1(23.5,12.7) v1(23.5,10.79) v1(24.13,76.2) v1(24.64,4.45) v1(25.4,78.11) v1(25.4,69.22) v1(25.4,66.67) v1(25.4,10.79) v1(25.53,3.81) v1(27.3,81.28) v1(27.3,79.38) v1(27.3,10.79) v1(27.43,98.55) v1(27.43,97.66) v1(27.94,75.56) v1(27.94,60.33) v1(27.94,58.42) v1(27.94,56.52) v1(27.94,54.61) v1(28.32,96.14) v1(28.57,78.11) v1(29.21,113.79) v1(29.21,111.76) v1(29.21,109.22) v1(29.21,74.3) v1(29.21,10.79) v1(29.84,76.83) v1(29.84,0.76) v1(29.97,95.25) v1(29.97,93.22) v1(30.86,91.82) v1(30.86,90.3) v1(30.99,97.57) v1(30.99,96.18) v1(31.75,113.79) v1(31.75,111.76) v1(31.75,109.22) v1(31.75,0.76) v1(33.66,0.76) v1(34.29,113.79) v1(34.29,111.76) v1(34.29,109.22) v1(34.42,95.5) v1(34.42,91.19) v1(34.42,86.23) v1(34.42,81.66) v1(34.54,93.34) v1(34.54,89.41) v1(34.54,87.88) v1(34.54,84.71) v1(34.54,83.19) v1(34.92,80.64) v1(35.56,0.76) v1(35.94,94.61) v1(35.94,64.39) v1(35.94,60.58) v1(35.94,57.4) v1(36.07,92.08) v1(36.2,89.92) v1(36.2,84.71) v1(36.2,83.06) v1(36.45,87.88) v1(36.45,86.36) v1(36.7,6.1) v1(36.83,113.79) v1(36.83,111.76) v1(36.83,109.22) v1(36.83,55.24) v1(36.86,3.68) v1(37.47,95.25) v1(37.47,92.71) v1(37.47,7.62) v1(37.59,59.69) v1(37.85,4.83) v1(38.1,68.58) v1(38.1,57.28) v1(38.1,0.76) v1(38.35,106.81) v1(38.73,53.85) v1(39.24,3.81) v1(39.37,63.5) v1(39.37,60.96) v1(39.37,5.71) v1(40.01,95.25) v1(40.01,92.71) v1(40.01,66.67) v1(40.64,58.42) v1(40.64,56.01) v1(40.64,0.76) v1(41.27,50.04) v1(41.27,48.9) v1(41.27,47.62) v1(41.27,46.35) v1(41.27,45.09) v1(41.27,43.81) v1(41.27,27.3) v1(41.27,5.71) v1(41.91,64.77) v1(41.91,60.96) v1(42.29,106.81) v1(42.55,97.79) v1(42.55,95.25) v1(42.55,92.71) v1(42.55,90.17) v1(42.55,87.63) v1(42.55,29.84) v1(42.55,28.57) v1(42.55,27.3) v1(42.55,0.76) v1(43.18,59.69) v1(43.18,18.41) v1(43.81,48.9) v1(43.81,47.62) v1(43.81,46.35) v1(43.81,45.09) v1(44.45,97.79) v1(44.45,95.25) v1(44.45,92.71) v1(44.45,90.17) v1(44.45,71.25) v1(44.45,29.84) v1(44.45,28.57) v1(44.45,27.3) v1(44.45,18.41) v1(44.45,0.76) v1(46.35,69.85) v1(46.35,29.84) v1(46.35,28.57) v1(46.35,27.3) v1(46.35,18.41) v1(46.35,16.51) v1(46.35,15.24) v1(46.39,9.02) v1(46.35,0.76) v1(46.74,106.68) v1(46.99,97.79) v1(46.99,95.25) v1(46.99,92.71) v1(46.99,83.82) v1(46.99,81.28) v1(47.4,9.02) v1(47.62,18.41) v1(47.62,16.51) v1(47.62,15.24) v1(48.04,10.03) v1(48.26,67.94) v1(48.26,29.84) v1(48.26,28.57) v1(48.26,27.3) v1(48.67,9.02) v1(48.9,18.41) v1(48.9,16.51) v1(48.9,15.24) v1(48.9,13.97) v1(48.9,0.76) v1(49.53,95.25) v1(49.53,85.09) v1(49.53,82.55) v1(49.53,80.01) v1(49.53,66.67) v1(49.94,9.02) v1(49.94,7.87) v1(50.16,18.41) v1(50.16,16.51) v1(50.16,15.24) v1(50.16,13.97) v1(51.21,9.02) v1(51.21,7.87) v1(51.44,29.84) v1(51.44,28.57) v1(51.44,0.76) v1(52.2,106.68) v1(52.48,10.29) v1(52.48,9.02) v1(52.48,7.87) v1(53.34,43.18) v1(53.34,0.76) v1(53.72,29.84) v1(53.75,15.24) v1(53.75,14.1) v1(53.75,10.29) v1(53.75,9.02) v1(53.75,7.87) v1(53.98,50.8) v1(54.1,35.43) v1(54.61,66.04) v1(54.61,49.53) v1(55.02,15.24) v1(55.02,14.1) v1(55.24,0.76) v1(55.88,58.42) v1(55.88,55.88) v1(56.9,57.28) v1(57.02,106.68) v1(57.15,0.76) v1(57.66,66.93) v1(57.82,15.75) v1(57.82,14.61) v1(57.82,13.21) v1(57.82,11.68) v1(57.82,10.03) v1(57.82,8.38) v1(57.82,7.37) v1(57.95,4.23) v1(57.95,3.43) v1(58.42,58.42) v1(58.42,55.88) v1(58.42,54.48) v1(58.83,4.23) v1(58.83,3.43) v1(59.22,14.1) v1(59.22,10.03) v1(59.22,8.38) v1(59.22,7.37) v1(59.34,11.68) v1(59.69,0.76) v1(59.85,4.23) v1(59.85,3.43) v1(60.45,57.66) v1(60.45,55.75) v1(60.58,11.68) v1(60.96,60.96) v1(61.47,28.07) v1(61.59,113.16) v1(62.23,110.49) v1(62.23,0.76) v1(63.15,13.77) v1(63.5,113.03) v1(63.91,13.77) v1(64.01,28.07) v1(64.14,0.76) v1(66.04,97.79) v1(66.04,0.76) v1(66.8,108.2) v1(67.31,99.06) v1(67.31,97.79) v1(67.31,96.52) v1(67.31,95.25) v1(67.31,66.04) v1(67.31,63.5) v1(67.31,60.96) v1(67.31,58.42) v1(67.31,55.88) v1(67.34,8.89) v1(67.34,6.86) v1(67.44,113.16) v1(67.69,16.26) v1(67.69,15.37) v1(67.69,14.48) v1(67.72,4.36) v1(67.72,3.56) v1(67.94,0.76) v1(68.36,9.78) v1(68.36,8.89) v1(68.36,7.87) v1(68.36,6.86) v1(68.58,99.19) v1(68.58,97.41) v1(68.58,96.52) v1(68.71,106.43) v1(68.74,4.36) v1(68.74,3.56) v1(69.2,18.82) v1(69.53,18.06) v1(69.85,66.04) v1(69.85,63.5) v1(69.85,60.96) v1(69.85,58.42) v1(69.85,55.88) v1(69.76,6.48) v1(69.76,5.59) v1(70.1,113.16) v1(70.23,106.43) v1(70.36,3.56) v1(70.48,0.76) v1(71.74,86.61) v1(71.74,85.6) v1(71.69,5.59) v1(72.26,108.2) v1(72.39,113.03) v1(72.75,87.63) v1(72.75,86.61) v1(72.75,85.6) v1(73.53,0.79) v1(73.79,111.76) v1(73.82,87.63) v1(73.82,86.61) v1(73.82,85.6) v1(73.82,6.35) v1(74.93,113.03) v1(75.44,9.14) v1(75.44,7.75) v1(75.69,6.6) v1(76.2,101.09) v1(76.2,99.69) v1(76.36,1.27) v1(76.71,101.98) v1(76.96,111.63) v1(77.47,113.03) v1(77.47,104.78) v1(78.74,104.78) v1(78.9,3.81) v1(78.9,1.27) v1(79.38,48.9) v1(80.01,104.78) v1(80.01,20.95) v1(80.77,84.2) v1(80.77,82.68) v1(80.77,81.28) v1(80.77,79.63) v1(80.77,78.36) v1(80.9,25.65) v1(80.9,24.51) v1(80.9,22.86) v1(80.9,21.84) v1(81.28,39.37) v1(81.44,3.81) v1(81.44,1.27) v1(81.66,111) v1(81.69,36.2) v1(81.79,23.62) v1(81.79,20.95) v1(81.92,113.03) v1(83.57,107.57) v1(83.98,66.04) v1(83.98,63.5) v1(83.98,54.61) v1(83.98,52.07) v1(83.98,49.53) v1(85.98,25.65) v1(85.98,22.73) v1(86.36,56.52) v1(86.36,28.32) v1(86.49,67.56) v1(86.52,66.04) v1(86.52,62.23) v1(86.52,59.69) v1(86.52,54.61) v1(86.52,52.07) v1(86.52,49.53) v1(86.61,106.55) v1(86.61,19.81) v1(86.61,16.76) v1(86.61,14.86) v1(86.61,12.95) v1(86.61,11.18) v1(87,31.11) v1(87.25,104.01) v1(87.79,29.21) v1(87.79,26.67) v1(87.79,24.13) v1(87.79,21.59) v1(88.52,19.94) v1(88.52,16.76) v1(88.52,14.86) v1(88.52,12.95) v1(88.52,11.18) v1(88.77,30.99) v1(88.77,28.32) v1(88.9,106.68) v1(88.9,104.14) v1(88.9,25.4) v1(88.9,22.86) v1(89.06,78.74) v1(89.06,76.2) v1(89.06,73.66) v1(89.06,71.12) v1(89.06,68.58) v1(89.06,66.04) v1(89.06,62.23) v1(89.06,59.69) v1(89.06,57.15) v1(89.06,54.61) v1(89.06,52.07) v1(89.06,49.53) v1(89.15,100.71) v1(89.15,97.54) v1(89.15,93.98) v1(89.15,90.93) v1(89.15,87.76) v1(89.15,82.55) v1(89.15,80.14)
